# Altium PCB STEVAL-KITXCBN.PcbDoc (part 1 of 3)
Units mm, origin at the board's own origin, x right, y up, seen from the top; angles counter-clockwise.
Board outline 110 x 100 mm, 4 copper layers (Top Layer, GND, PWR, Bottom Layer), stack 1.53 mm thick; 227 components, 137 nets, 699 pads, 698 vias.
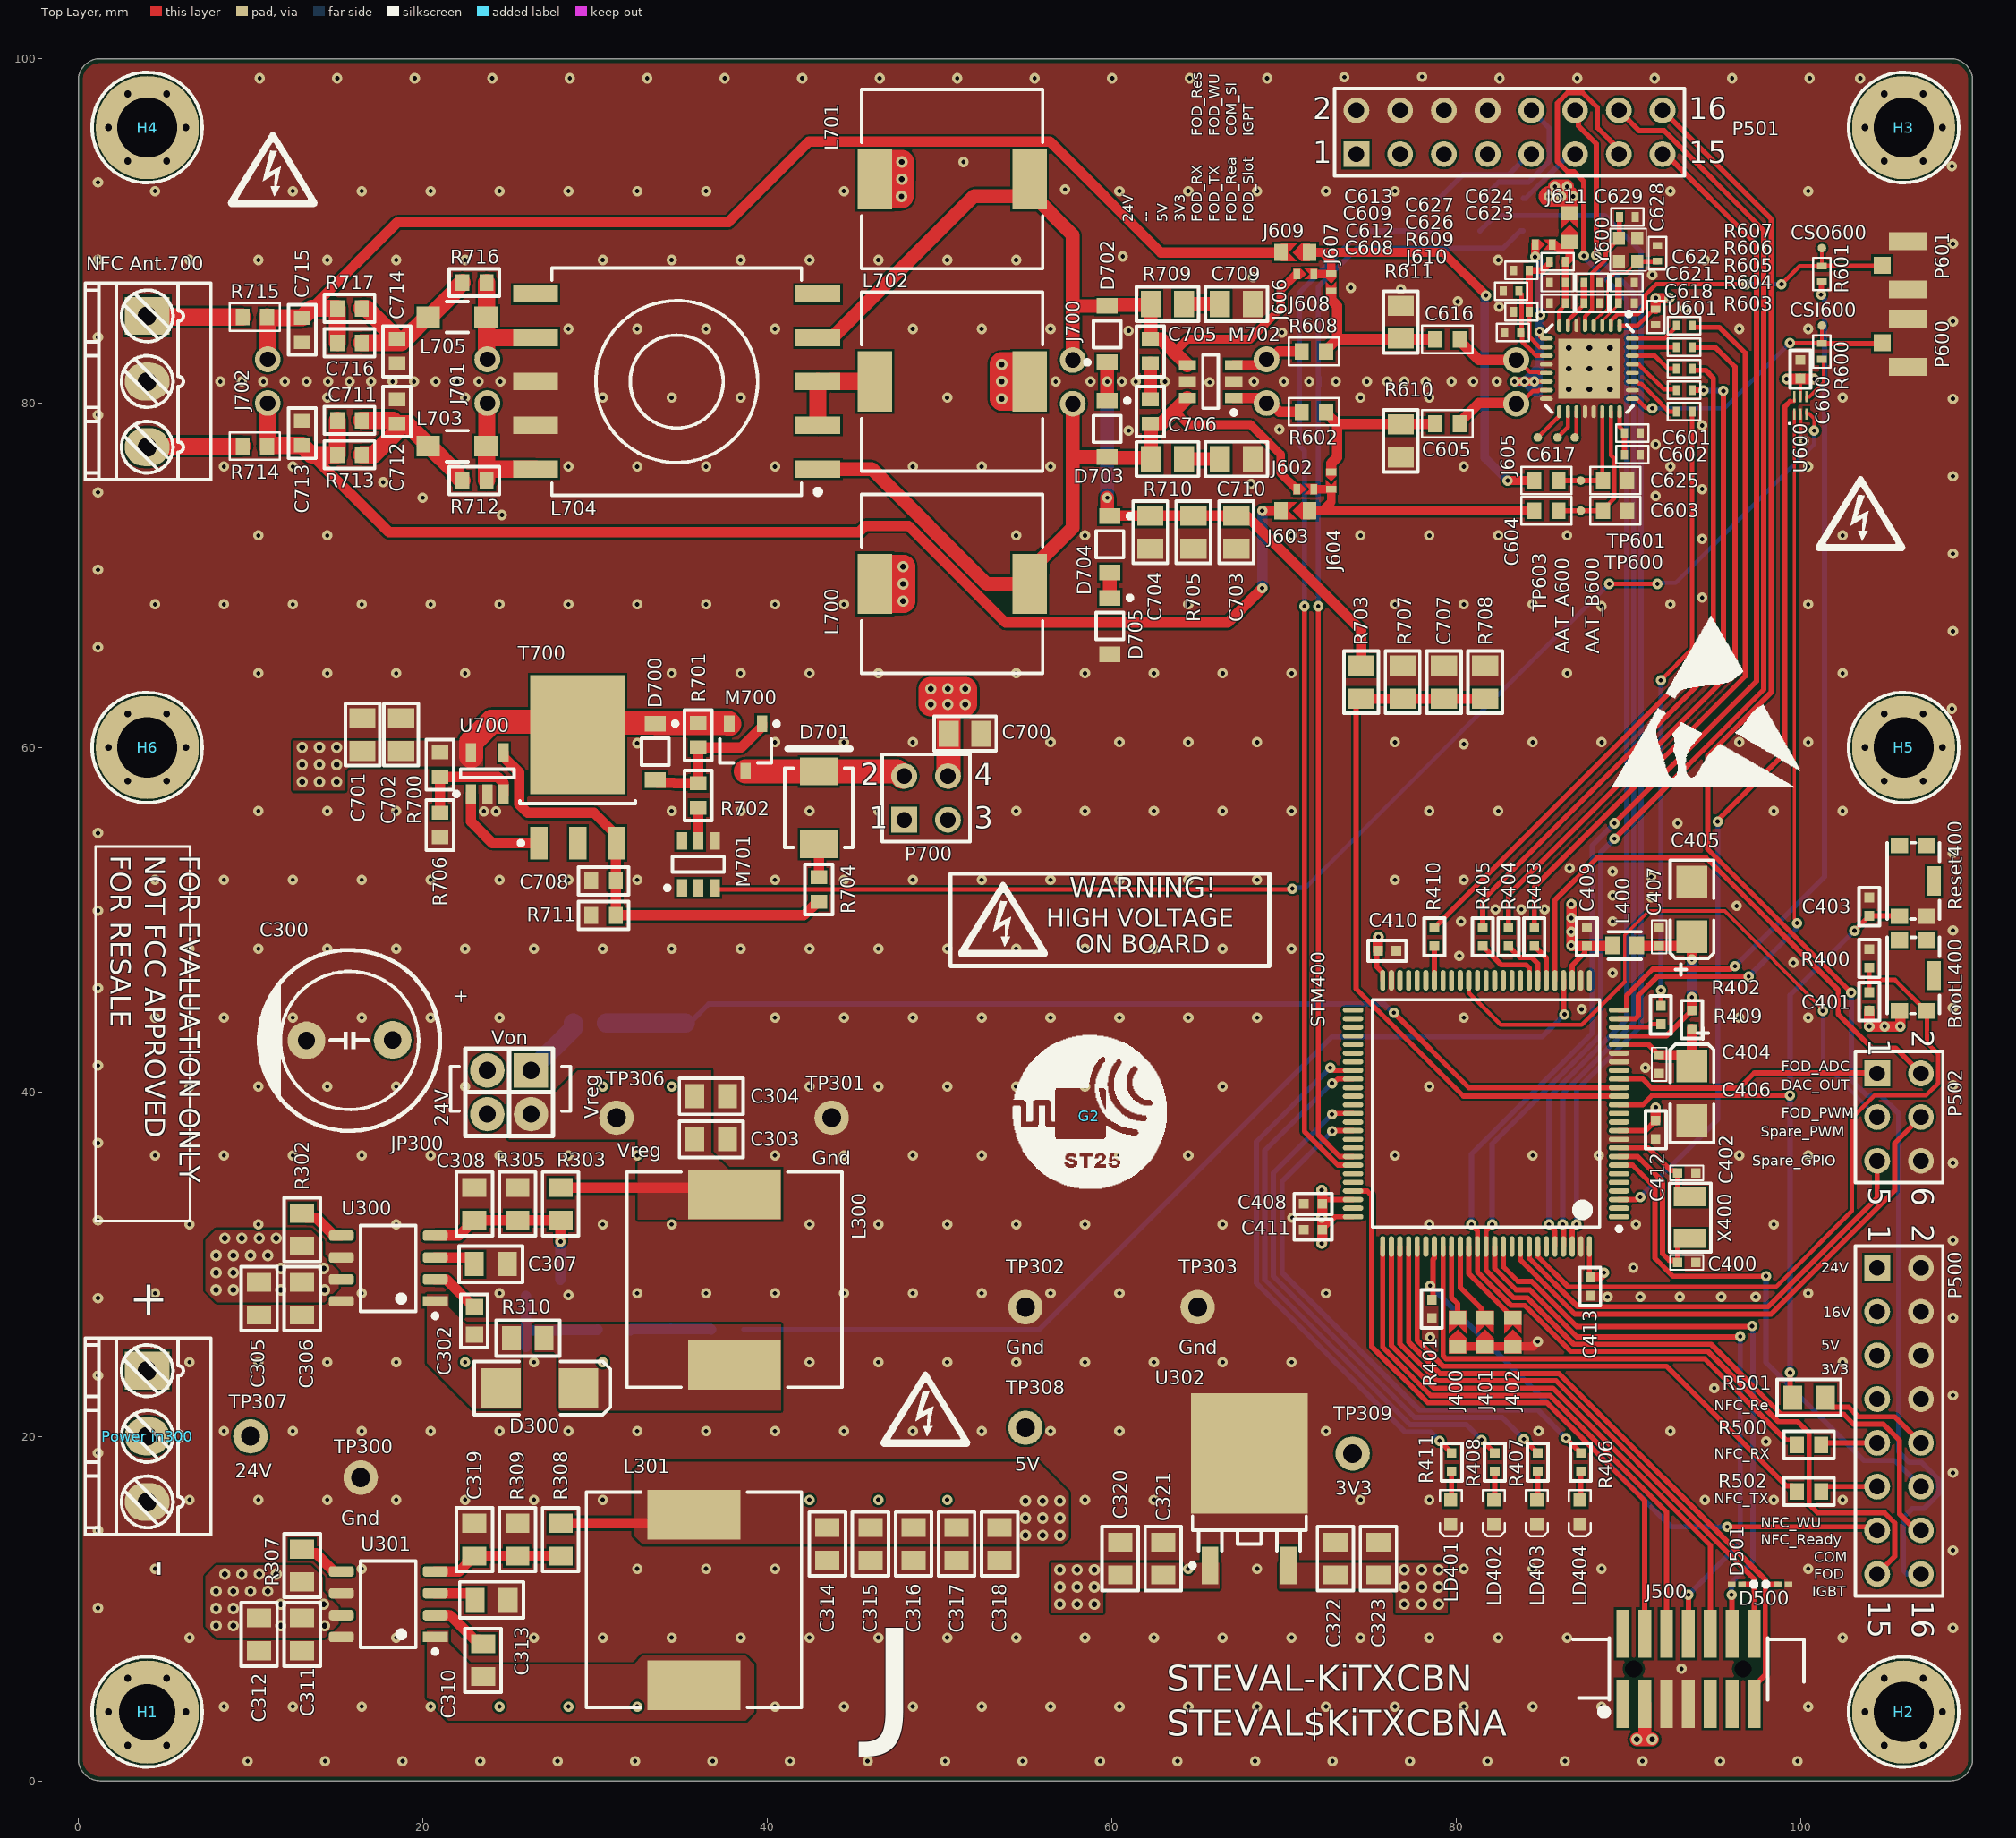
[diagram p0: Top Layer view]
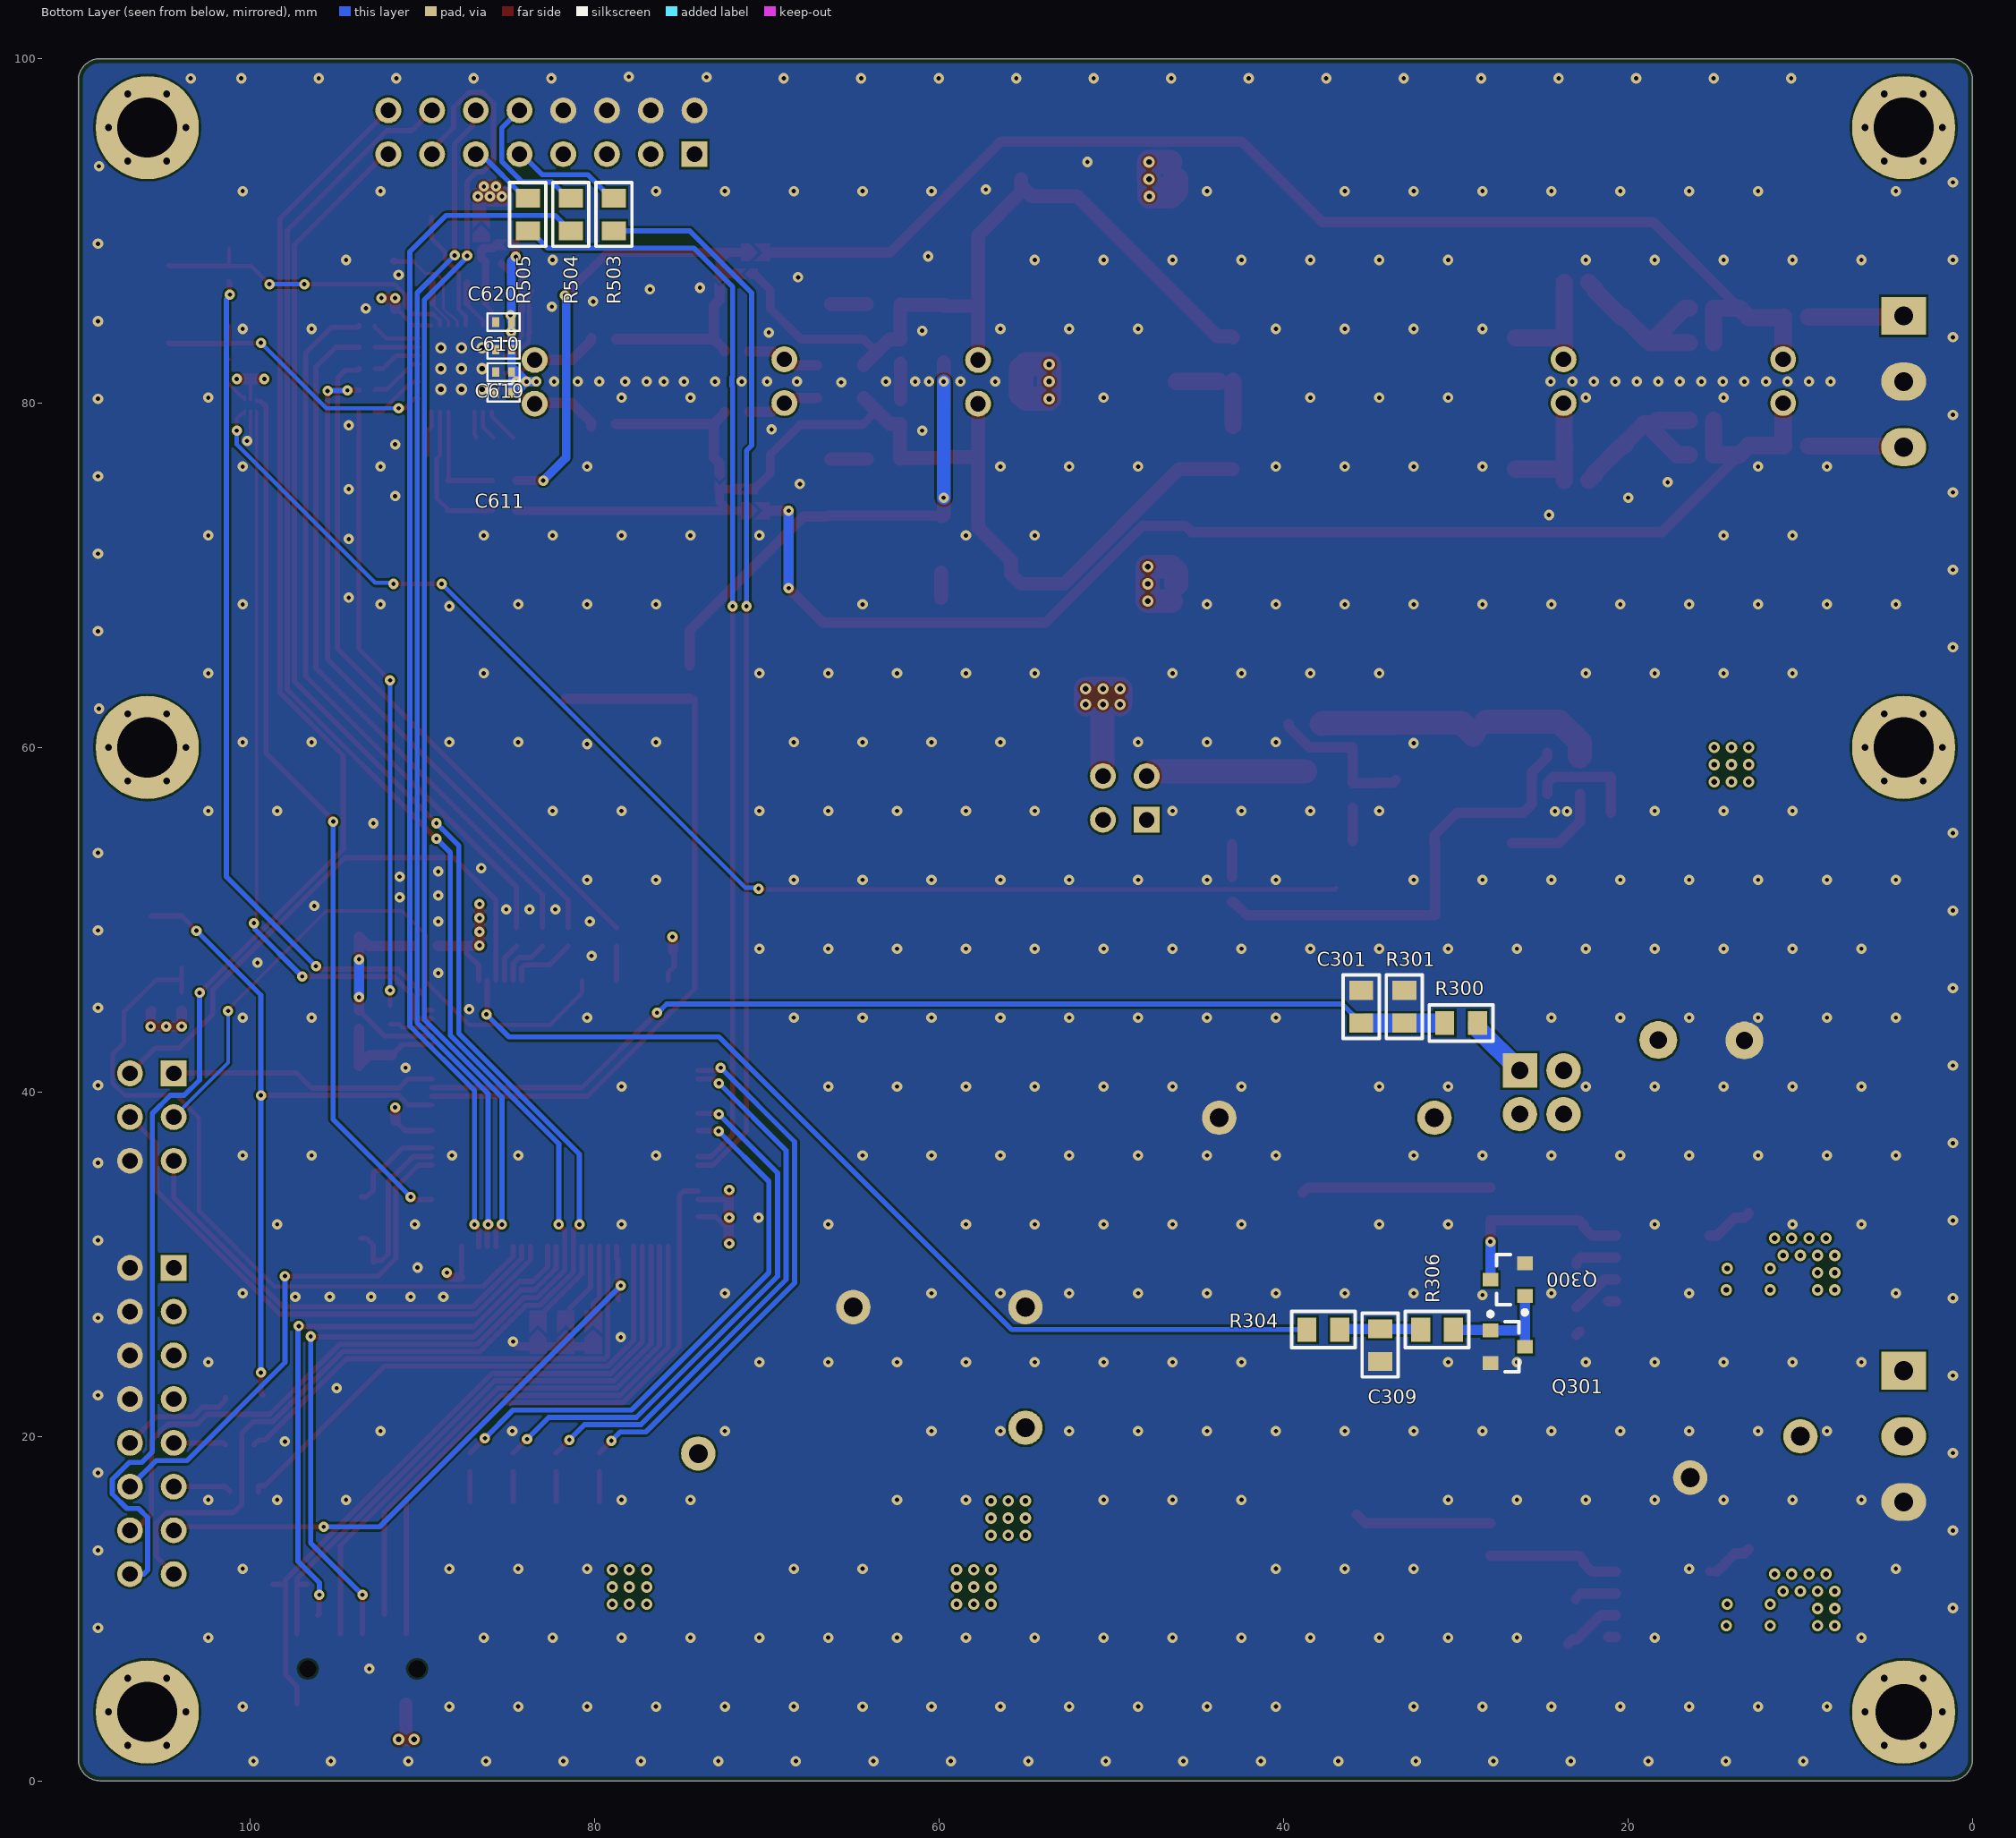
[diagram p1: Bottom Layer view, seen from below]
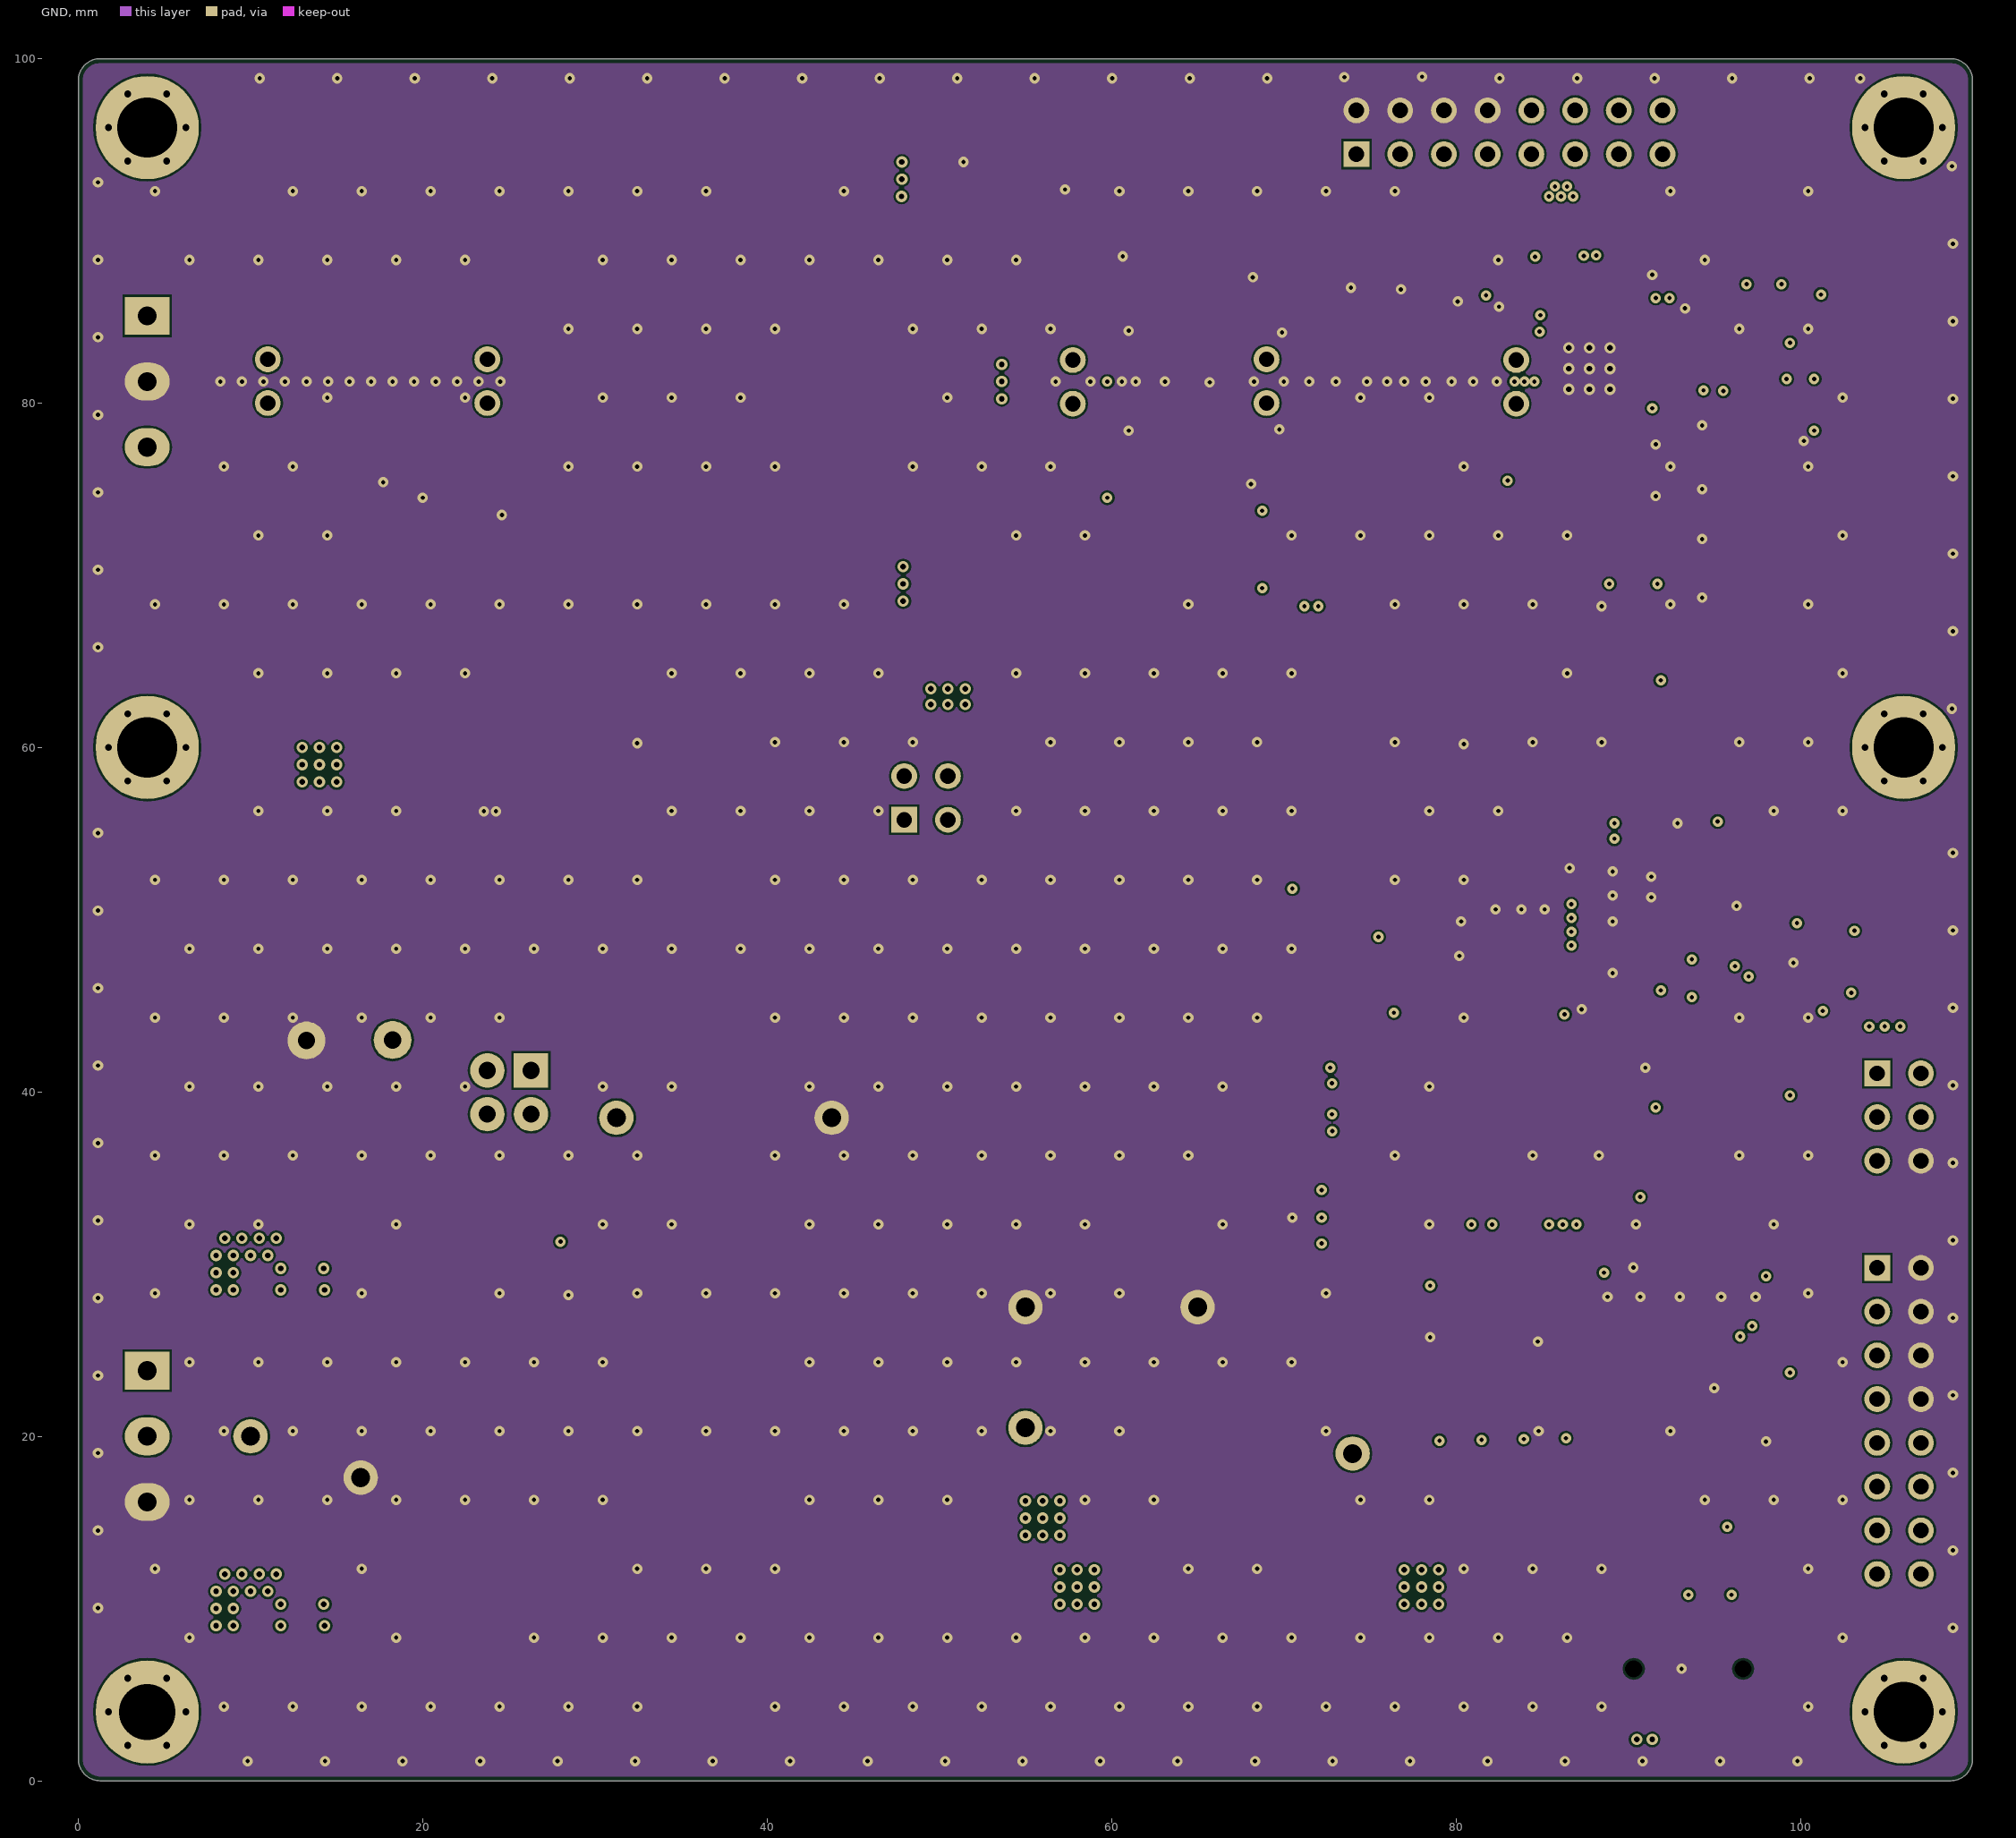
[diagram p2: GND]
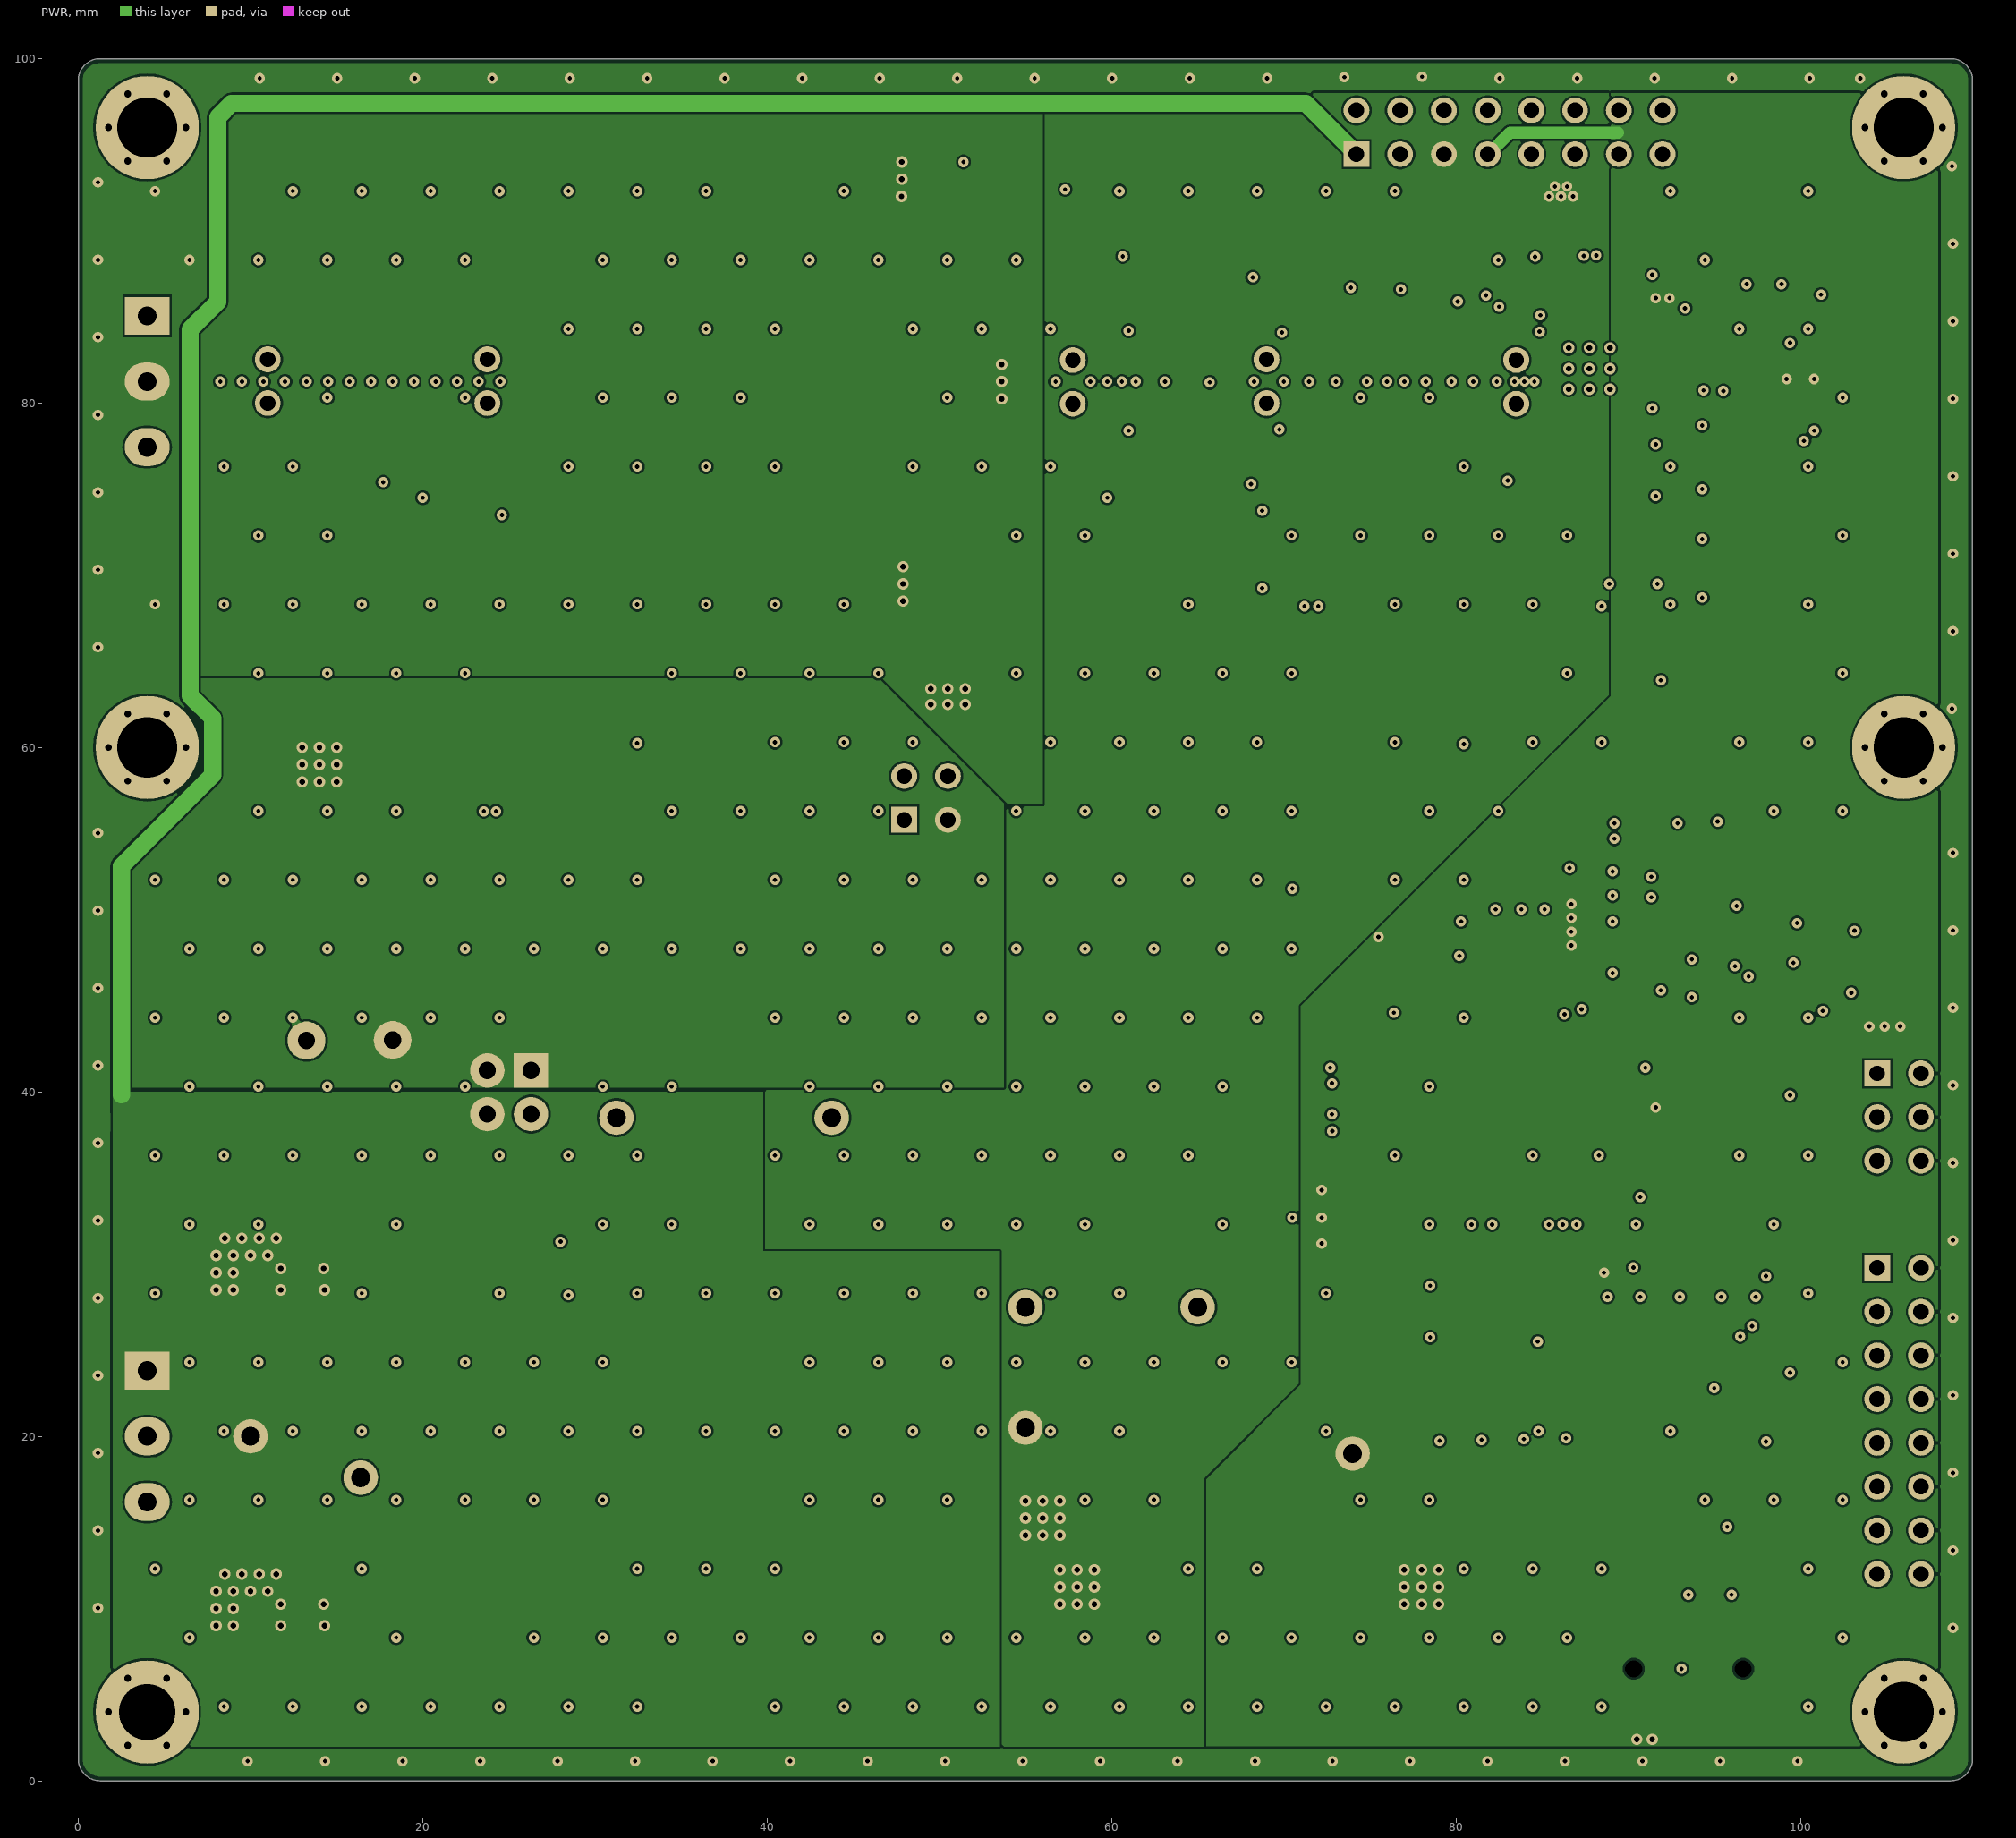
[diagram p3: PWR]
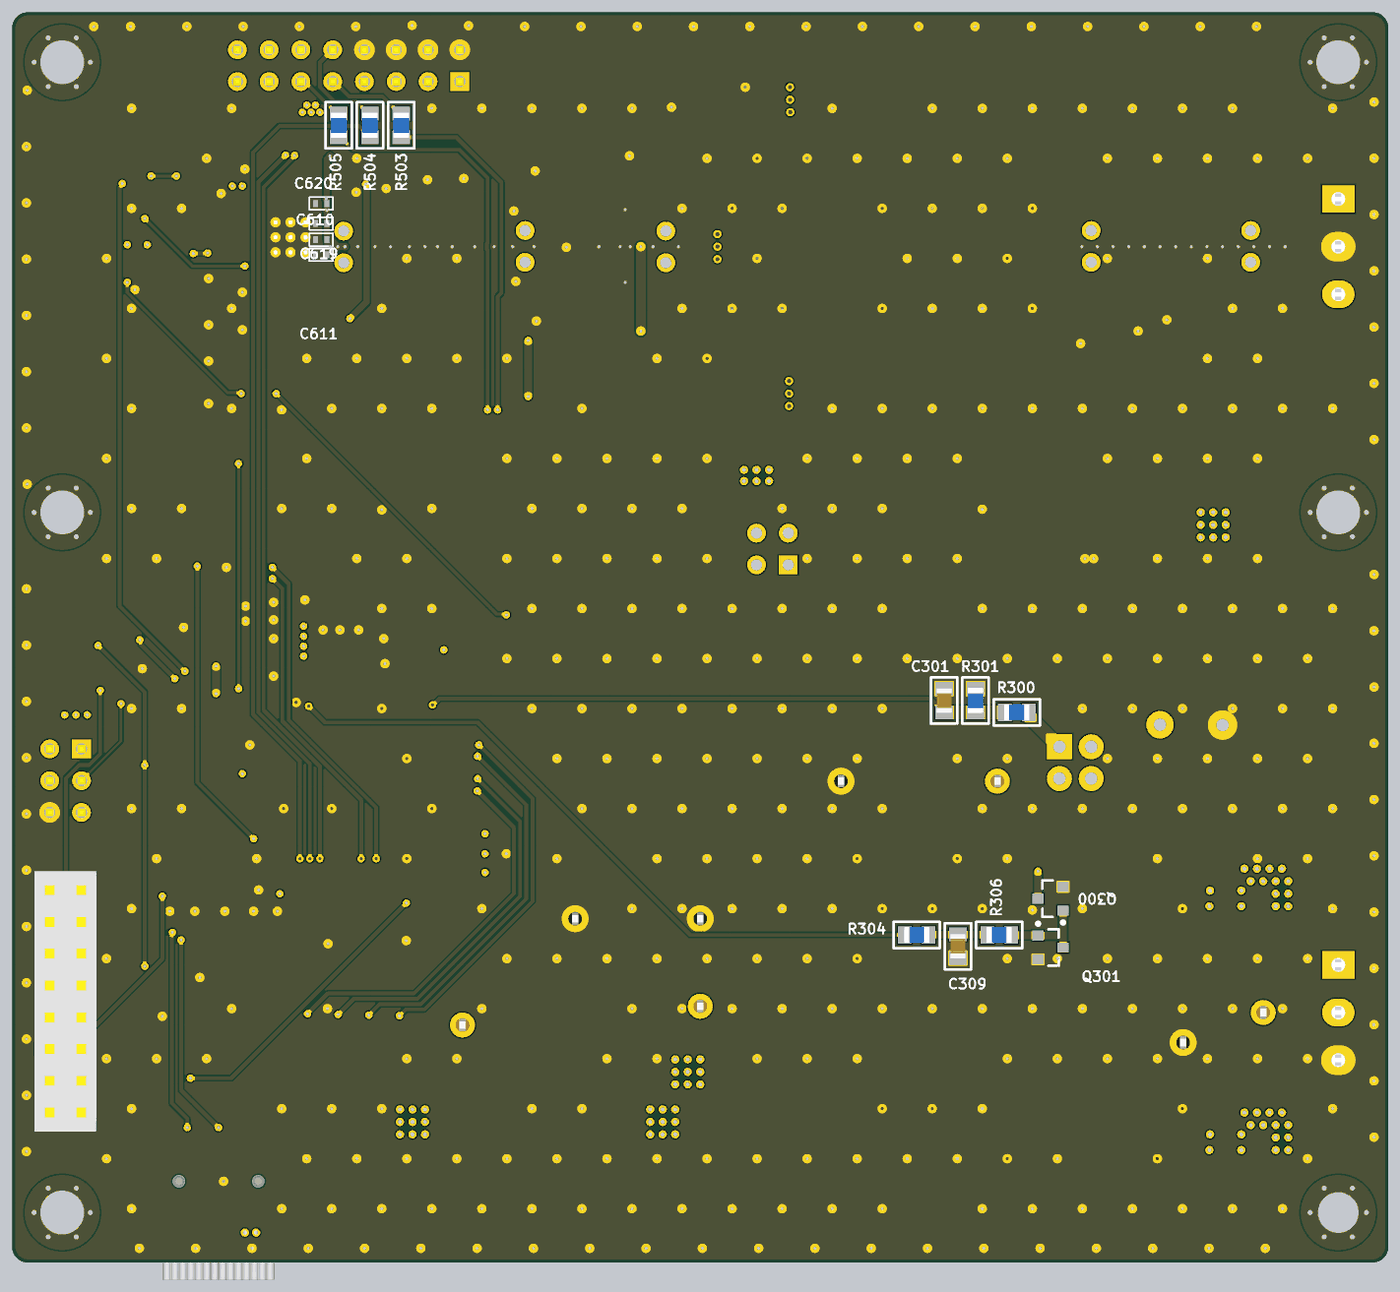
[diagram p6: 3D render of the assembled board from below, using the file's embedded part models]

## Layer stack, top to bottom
Top Solder: solder mask 0.01, Solder Resist, Dk 3.5
Top Layer: signal copper 0.035
Dielectric 1: core 0.62, FR-4, Dk 4.4
GND: signal copper 0.035
Dielectric 3: prepreg 0.15, RF-4, Dk 4.4
PWR: signal copper 0.035
Dielectric 2: core 0.62, RF-4, Dk 4.4
Bottom Layer: signal copper 0.035
Bottom Solder: solder mask 0.01, Solder Resist, Dk 3.5

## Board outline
0,1.27 0,98.73 cw(c1.27,98.73) 1.27,100 108.73,100 cw(c108.73,98.73) 110,98.73 110,1.27 cw(c108.73,1.27) 108.73,0 1.27,0 cw(c1.27,1.27)

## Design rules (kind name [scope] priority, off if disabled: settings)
BoardOutlineClearance [All] p1: gap=0.254 ignorepadtopadclearanceinfootprint=FALSE except(0: Arc-SplitContinuation Track-SplitContinuation SMDPad-SplitContinuation THPad-SplitContinuation Via-SplitContinuation Fill-SplitContinuation Poly-SplitContinuation Region-SplitContinuation Text-SplitContinuation)
Clearance "Stitching GND" [IsStitchingVia and InNet('GND') vs (IsVia and (Not IsStitchingVia)) Or IsPad] p1: gap=0.127 ignorepadtopadclearanceinfootprint=FALSE
Clearance [All] p2: gap=0.125 ignorepadtopadclearanceinfootprint=FALSE except(0: Arc-Hole Track-Hole SMDPad-Hole THPad-Hole Via-Hole Fill-Hole Poly-Hole Region-Hole Text-Hole)
DiffPairsRouting [All] p1: maxlimit=10 minlimit=0.125 mostfreqgap=0.15 toplayer_minwidth=0.381 toplayer_maxwidth=0.381 toplayer_prefwidth=0.381 midlayer1_minwidth=0.381 midlayer1_maxwidth=0.381 midlayer1_prefwidth=0.381 midlayer2_minwidth=0.381 midlayer2_maxwidth=0.381 midlayer2_prefwidth=0.381 bottomlayer_minwidth=0.381 bottomlayer_maxwidth=0.381 bottomlayer_prefwidth=0.381 maxuncoupledlength=12.7
FabricationTestPointUsage FabricationTestPointUsage_1 [All] p1: valid=0 allowmultiple=FALSE
FabricationTestpoint FabricationTestpoint_1 [All] p1: side=3 testpointundercomponent=TRUE minsize=1.016 maxsize=2.54 preferedsize=1.524 minholesize=0 maxholesize=1.016 preferedholesize=0.813 testpointgrid=0.025 allowsidetop=TRUE allowsidebottom=TRUE usegrid=TRUE gridtolerance=0
HoleSize [All] p1: absolutevalues=TRUE maxlimit=6 minlimit=0.2 maxpercent=80.000 minpercent=20.000
HoleSize FabricationTestpoint [All] p2 off: absolutevalues=TRUE maxlimit=2.54 minlimit=0.025 maxpercent=80.000 minpercent=20.000
HoleSize FabricationTestPointUsage [All] p3 off: absolutevalues=TRUE maxlimit=2.54 minlimit=0.025 maxpercent=80.000 minpercent=20.000
PlaneClearance [All] p1: clearance=0.5
PlaneConnect [All] p1: planeconnectstyle=Relief reliefexpansion=0.4 reliefentries=4 reliefconductorwidth=0.15 reliefairgap=0.15
PolygonConnect [All] p1: connectstyle=Direct reliefconductorwidth=0.15 reliefentries=4 polygonreliefangle="90 Angle" airgapwidth=0.254
RoutingCorners [All] p1: cornerstyle=45-Degree minsetback=1.25 maxsetback=1.25
RoutingVias [All] p1: holewidth=0.3 width=0.6 viastyle="Through Hole" minholewidth=0.2 minwidth=0.45 maxholewidth=0.45 maxwidth=0.75
SolderMaskExpansion SolderMaskExpansion_isvia [IsVia] p1: expansion=0.1 istentingtop=FALSE soldermaskfromhole=TRUE
SolderMaskExpansion [All] p2: expansion=0.075 istentingtop=FALSE
Width [All] p1: maxlimit=10 minlimit=0.125 preferedwidth=0.15
23 further rules are at their usual default settings.

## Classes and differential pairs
component class Designator: AAT_A600 AAT_B600 C600 C601 C602 C603 C604 C605 C608 C609 C610 C611 C612 C613 C616 C617 C618 C619 C620 C621 C622 C623 C624 C625 C626 C627 C628 C629 CSI600 CSO600 J602 J603 J604 J605 J606 J607 J608 J609 J610 J611 P600 P601 R600 R601 R602 R603 R604 R605 R606 R607 R608 R609 R610 R611 TP600 TP601 TP603 U600 U601 Y600
component class "Project Page_Ki_Main_V1_3": Coil1 D6 D8 D9 D10 D11 G2 H1 H2 H3 H4 H5 H6 J?1 R10 U?1

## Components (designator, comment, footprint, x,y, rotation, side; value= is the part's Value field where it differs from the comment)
AAT_A600 "*" TP_0.5 85.9,78 r90 top
AAT_B600 "*" TP_0.5 86.9,78 r90 top
BootL400 "PushButton" SW_SPST_KMR211G 107.35,44.7 r270 top
C300 "100uF" "ECAP 10XP5  H14" 15.75,43 r90 top
C301 "100nF" CAP_SMD_0805 35.5,44.95 r270 bottom
C302 "100nF" CAP_SMD_0603 23,26.7 r270 top
C303 "10uF" CAP_SMD_0805 36.75,37.25 r180 top
C304 "10uF" CAP_SMD_0805 36.75,39.75 r180 top
C305 "100nF" CAP_SMD_0805 10.5,28 r90 top
C306 "10uF" CAP_SMD_0805 13,28 r90 top
C307 "1uF" CAP_SMD_0805 23.95,30 r0 top
C308 "10pF" CAP_SMD_0805 23,33.5 r90 top
C309 "1uF" CAP_SMD_0805 34.4,25.3 r270 bottom
C310 "100nF" CAP_SMD_0805 23.5,7 r90 top
C311 "1uF" CAP_SMD_0805 13,8.5 r270 top
C312 "10uF" CAP_SMD_0805 10.5,8.5 r90 top
C313 "1uF" CAP_SMD_0805 24,10.5 r0 top
C314 "10uF" CAP_SMD_0805 43.5,13.75 r90 top
C315 "10uF" CAP_SMD_0805 46,13.75 r90 top
C316 "10uF" CAP_SMD_0805 48.5,13.75 r90 top
C317 "10uF" CAP_SMD_0805 51,13.75 r90 top
C318 "100nF" CAP_SMD_0805 53.5,13.75 r90 top
C319 "10pF" CAP_SMD_0805 23,14 r90 top
C320 "100nF" CAP_SMD_0805 60.5,12.9 r270 top
C321 "1uF" CAP_SMD_0805 63,12.9 r90 top
C322 "1uF" CAP_SMD_0805 73,12.9 r90 top
C323 "100nF" CAP_SMD_0805 75.5,12.9 r270 top
C400 "18pF" C0402#1 93.4,30.1 r0 top
C401 "100nF" C0402-ss 104,45.25 r90 top
C402 "18pF" C0402#1 93.4,35.3 r0 top
C403 "100nF" C0402-ss 104,50.75 r270 top
C404 "100nF" C0402#1 91.8,41.6 r270 top
C405 "1uF" CP_SMD_A 93.7,50.6 r90 top
C406 "1uF" CP_SMD_A 93.7,39.913 r270 top
C407 "100nF" C0402#1 91.8,49 r90 top
C408 "100nF" C0402-ss 71.7,33.5 r0 top
C409 "100nF" C0402-ss 87.6,49 r270 top
C410 "100nF" C0402-ss 76,48.2 r180 top
C411 "100nF" C0402-ss 71.7,32 r0 top
C412 "100nF" C0402-ss 91.6,37.8 r90 top
C413 "100nF" C0402-ss 87.8,28.7 r90 top
C600 "100nF" C0402-ss 100,81.965 r270 top
C601 "1uF" C0402#2 90.25,78.25 r0 top
C602 "10nF" C0402#2 90.25,77 r0 top
C603 "120pF" C0603 89.25,73.75 r180 top
C604 "10pF" C0603 85.25,73.75 r180 top
C605 "100nF" C0603 79.5,78.8 r180 top
C608 "10nF" C0402#2 83.3,84.1 r180 top
C609 "2u2F" C0402#2 83.2,86.5 r180 top
C610 "10nF" C0402#2 85.3,81.8 r0 bottom
C611 "4u7F" C0402#2 85.3,80.6 r0 bottom
C612 "10nF" C0402#2 83.8,85.3 r180 top
C613 "2u2F" C0402#2 83.8,87.7 r180 top
C616 "100nF" C0603 79.5,83.7 r180 top
C617 "10pF" C0603 85.25,75.5 r0 top
C618 "10nF" C0402#2 91.6,85 r270 top
C619 "d.n.p." C0402#2 85.3,83.1 r0 bottom
C620 "d.n.p." C0402#2 85.3,84.7 r0 bottom
C621 "10nF" C0402#2 89.9,85.8 r0 top
C622 "2u2F" C0402#2 89.9,87 r0 top
C623 "10nF" C0402#2 87.9,85.8 r0 top
C624 "2u2F" C0402#2 87.9,87 r0 top
C625 "120pF" C0603 89.25,75.5 r0 top
C626 "10nF" C0402#2 85.9,85.8 r180 top
C627 "2u2F" C0402#2 85.9,87 r180 top
C628 "10pF" C0402#2 91.7,88.7 r90 top
C629 "10pF" C0402#2 89.957,90.8 r0 top
C700 "1nF" C0805 51.5,60.8 r0 top
C701 "10µF" C0805 16.5,60.75 r90 top
C702 "10nF" C0805 18.75,60.75 r90 top
C703 "100nF" C0805 67.25,72.5 r270 top
C704 "68pF" C0805 62.25,72.5 r270 top
C705 "15pF" C0603 62.25,83 r270 top
C706 "22pF" C0603 62.25,79.5 r270 top
C707 "100nF" C0805 79.3,63.8 r90 top
C708 "47nF" C0603 30.5,52.25 r0 top
C709 "33pF" C0805 67.25,85.75 r0 top
C710 "33pF" C0805 67.25,76.75 r0 top
C711 "2n2F" C0603 15.75,79 r180 top
C712 "22pF" C0603 18.5,79.5 r90 top
C713 "130pF" C0603 13,78.25 r90 top
C714 "22pF" C0603 18.5,83 r90 top
C715 "130pF" C0603 13,84.25 r90 top
C716 "2n2F" C0603 15.75,83.5 r180 top
CSI600 "*" TP_0.5 101.25,84.5 r90 top
CSO600 "*" TP_0.5 101.25,89 r90 top
D300 "Schottky" SMB 26.8,22.8 r0 top
D500 "ESDALC6V1-1U2" ST-ST0201 99,11.4 r90 top
D501 "ESDALC6V1-1U2" ST-ST0201 96.3,11.4 r270 top
D700 "" ONSC-SOD-123-2-425-04_V 33.5,59.75 r270 top
D701 "STPS2L25U" STM-SMB_P_V 43,56.5 r90 top
D702 "MMSD4148T1G" ONSC-SOD-123-2-425-04_V 59.75,84 r90 top
D703 "MMSD4148T1G" ONSC-SOD-123-2-425-04_V 59.75,78.5 r270 top
D704 "" ONSC-SOD-123-2-425-04_V 59.9,71.8 r270 top
D705 "" ONSC-SOD-123-2-425-04_V 59.9,67.05 r270 top
G2 "Logo_ST25" Logo_ST25 58.7,38.6 r0 top
H1 "Mounting Hole" HOLE_M3#1 4,4 r0 top
H2 "Mounting Hole" HOLE_M3#2 106,4 r0 top
H3 "Mounting Hole" HOLE_M3#2 106,96 r0 top
H4 "Mounting Hole" HOLE_M3#2 4,96 r0 top
H5 "Mounting Hole" HOLE_M3#2 106,60 r0 top
H6 "Mounting Hole" HOLE_M3#2 4,60 r0 top
J400 "open" JP2_SMD_open 80.1,26.05 r90 top
J401 "open" JP2_SMD_open 81.7,26.05 r90 top
J402 "open" JP2_SMD_open 83.3,26.05 r90 top
J500 "FTSH-107-01-L-DV-K-A" SAMTEC-FTSH-107-01-X-DV-K-A-WITH-FFSD 93.5,6.5 r0 top
J602 "open" JP2_SMD_open_0402 71.25,75 r0 top net-tie
J603 "closed 0R" JP2_SMD_closed 70.668,73.75 r180 top net-tie
J604 "open" JP2_SMD_open_0402 72.75,75.5 r270 top net-tie
J605 "d.n.p." HDR1X2_slim 83.5,79.96 r270 top
J606 "d.n.p." HDR1X2_slim 69,80 r270 top
J607 "open" JP2_SMD_open_0402 72.75,87 r270 top net-tie
J608 "open" JP2_SMD_open_0402 71.25,87.5 r0 top net-tie
J609 "closed 0R" JP2_SMD_closed 70.668,88.75 r180 top net-tie
J610 "open" JP2_SMD_open_0402 85.1,89.2 r0 top net-tie
J611 "closed 0R" JP2_SMD_closed 86.6,90.2 r90 top net-tie
J700 "d.n.p." HDR1X2_slim 57.75,79.96 r270 top
J701 "d.n.p." HDR1X2_slim 23.75,80 r270 top
J702 "d.n.p." HDR1X2_slim 11,80 r270 top
JP300 "TSW-102-07-G-D" Jump2V 26.29,41.25 r180 top
L300 "56uH" WE-PD-L 38.1,29.1 r90 top
L301 "33uH" WE-PD-L 35.75,10.5 r90 top
L400 "Ferrite Bead" 0603-CAP 89.8,48.5 r90 top value=BLM18AG601SN1D
L700 "7447714100" "WE-PD 1050" 50.75,69.5 r180 top value=10u
L701 "7447714100" "WE-PD 1050" 50.75,93 r180 top value=10u
L702 "7447714100" "WE-PD 1050" 50.75,81.25 r0 top value=10u
L703 "470n" FP-LQM31PN_00-MFG 22,77.5 r180 top
L704 "Cooktop Balun" "Wurth Cooktop Balun" 34.75,81.25 r180 top value=Balun
L705 "470n" FP-LQM31PN_00-MFG 22,85 r180 top
LD401 "White LED" 0603D 79.7,15.6 r270 top
LD402 "White LED" 0603D 82.2,15.6 r270 top
LD403 "White LED" 0603D 84.7,15.6 r270 top
LD404 "White LED" 0603D 87.2,15.6 r270 top
M700 "SSM3J353F,LF" "RSR020P05 SOT23-3L" 38.75,60 r270 top
M701 "NMOS STT6N3LLH6" "STT6N3LLH6 SOT23-6L" 36,53.211 r90 top
M702 "QS6K21FRATR" "NDC7002N TSOT23 6-Lead" 65.75,81.25 r180 top
"NFC Ant.700" "Screw Terminal" "TERMINAL MKDS 1/ 3-3.81" 4,81.25 r90 top locked value="MKDS 1/3-3.81"
P500 "Header 8X2_3D_female" HDR2X8_3D_female 104.46,29.78 r270 top
P501 "Header 8X2_3D_male" HDR2X8_3D_male 74.22,94.455 r0 top
P502 "Header 3X2_3D_male" HDR2X3_3D_male 104.46,41.08 r270 top
P600 "U.FL-R-SMT-1" "U FL Socket - HRS - Surface Mount" 105.75,83.5 r180 top
P601 "U.FL-R-SMT-1" "U FL Socket - HRS - Surface Mount" 105.75,88 r180 top
P700 "Header 2X2" HDR2X2 47.96,55.8 r0 top value=0
"Power in300" "Screw Terminal" "TERMINAL MKDS 1/ 3-3.81" 4,20 r90 top locked value="MKDS 1/3-3.81"
Q300 "BC846BLT1G" ONSC-SOT-23-3-318-08_V 27,29.1 r0 bottom
Q301 "BC846BLT1G" ONSC-SOT-23-3-318-08_V 27,25.2 r180 bottom
R300 "100k" RES_SMD_0805 29.7,44 r180 bottom
R301 "10k" RES_SMD_0805 33,44.95 r270 bottom
R302 "10k" RES_SMD_0805 13,32 r270 top
R303 "150k" RES_SMD_0805 28,33.5 r90 top
R304 "1k" RES_SMD_0805 37.7,26.2 r180 bottom
R305 "33k" RES_SMD_0805 25.5,33.5 r270 top
R306 "20k" RES_SMD_0805 31.1,26.2 r0 bottom
R307 "10k" RES_SMD_0805 13,12.5 r270 top
R308 "402kR" RES_SMD_0805 28,14 r90 top
R309 "82kR" RES_SMD_0805 25.5,14 r270 top
R310 "820" RES_SMD_0805 26.1,25.7 r180 top
R400 "10kR" R0402#1 104,47.75 r270 top
R401 "10kR" R0402#1 78.6,27.4 r90 top
R402 "0R" R0402#1 91.9,44.467 r270 top
R403 "0R" R0402#1 84.55,49 r270 top
R404 "0R" R0402#1 83.05,49 r270 top
R405 "0R" R0402#1 81.55,49 r270 top
R406 "120R" R0402#1 87.25,18.5 r270 top
R407 "120R" R0402#1 84.75,18.5 r270 top
R408 "120R" R0402#1 82.25,18.5 r270 top
R409 "47R" R0402#1 93.7,44.2 r270 top
R410 "0R" R0402#1 78.75,49 r270 top
R411 "120R" R0402#1 79.75,18.5 r270 top
R500 "100R" R0603 100.5,19.5 r0 top
R501 "220R" RES_SMD_0805 100.5,22.25 r180 top
R502 "100R" R0603 100.5,16.8 r0 top
R503 "0R" RES_SMD_0805 78.9,90.95 r90 bottom
R504 "220R" RES_SMD_0805 81.4,90.95 r270 bottom
R505 "0R" RES_SMD_0805 83.9,90.95 r90 bottom
R600 "50R" R0402#2 101.25,83 r90 top
R601 "50R" R0402#2 101.25,87.5 r90 top
R602 "0R" R0603 71.75,79.5 r180 top
R603 "0R" R0402#2 93.25,79.5 r0 top
R604 "0R" R0402#2 93.25,80.75 r0 top
R605 "0R" R0402#2 93.25,82 r0 top
R606 "0R" R0402#2 93.25,83.25 r0 top
R607 "0R" R0402#2 93.25,84.5 r0 top
R608 "0R" R0603 71.75,83 r180 top
R609 "0R" R0402#2 85.9,88.2 r180 top
R610 "10kR" R0805 76.8,77.8 r270 top
R611 "10kR" R0805 76.8,84.7 r270 top
R700 "10k" R0603 21,59 r270 top
R701 "2k" R0603 36,60.711 r270 top
R702 "4k2" R0603 36,57.211 r270 top
R703 "330kR" R0805 74.5,63.8 r270 top
R704 "2R" R0603 43,51.75 r270 top value=2
R705 "10kR" R0805 64.75,72.5 r270 top
R706 "40k2" R0603 21,55.5 r270 top
R707 "10kR" R0805 76.9,63.8 r90 top
R708 "d.n.p." R0805 81.7,63.8 r90 top
R709 "10R" R0805 63.25,85.75 r0 top
R710 "10R" R0805 63.25,76.75 r0 top
R711 "47kR" R0603 30.5,50.25 r180 top
R712 "100R" R0603 23,75.5 r180 top
R713 "1M" R0603 15.75,77 r180 top
R714 "0R" R0603 10.25,77.5 r180 top
R715 "0R" R0603 10.25,85 r180 top
R716 "100R" R0603 23,87 r180 top
R717 "1M" R0603 15.75,85.5 r180 top
Reset400 "PushButton" SW_SPST_KMR211G 107.35,50.2 r270 top
STM400 "STM32L476VGT6" "STM32L476VGT6 LQFP100" 81.75,38.75 r180 top
T700 "NPN STD1802T4" "STD1802 DPAK" 29,58.85 r90 top
TP300 "Gnd" TESTPOINT_BLACK 16.4,17.6 r90 top value=Testpoint
TP301 "Gnd" TESTPOINT_BLACK 43.75,38.5 r90 top value=Testpoint
TP302 "Gnd" TESTPOINT_BLACK 55,27.5 r90 top value=Testpoint
TP303 "Gnd" TESTPOINT_BLACK 65,27.5 r90 top value=Testpoint
TP306 "Vreg" TESTPOINT_RED 31.25,38.5 r90 top value=Testpoint
TP307 "24V" TESTPOINT_RED 10,20 r90 top value=Testpoint
TP308 "5V" TESTPOINT_RED 55,20.5 r90 top value=Testpoint
TP309 "3V3" TESTPOINT_RED 74,19 r90 top value=Testpoint
TP600 "*" TP_0.5 87.25,73.75 r90 top
TP601 "*" TP_0.5 87.25,75.5 r90 top
TP603 "*" TP_0.5 84.75,78 r90 top
U300 "L6981NDR" SOIC-8 18,29.75 r180 top
U301 "L6981NDR" SOIC-8 18,10.25 r180 top
U302 "LF33CDT" "TO-252 DPAK" 68,16.9 r0 top
U600 "74LVC1G3157" XSON6_SOT1202 100,79.865 r90 top
U601 "ST25R3916" ST25R3916-QFN32_5X5_0.5 87.75,82 r270 top
U700 "THS4304DBVTG4" TI-DBV5_N 23.75,58.5 r90 top
X400 "32_768kHz" 32_768kHz_Crystal 93.6,32.7 r270 top
Y600 "NDK 27,12MHz Crystal" XRCGB_F_MN 90,88.9 r90 top

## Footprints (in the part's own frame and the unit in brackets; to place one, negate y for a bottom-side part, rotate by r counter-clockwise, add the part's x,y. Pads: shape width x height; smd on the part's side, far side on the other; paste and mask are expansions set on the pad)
32_768kHz_Crystal [mm]
  rect 1.1x1.9 smd paste+0: 1(-1.2,0) 2(1.2,0)
  silkscreen extent -2,-1.2 2,1.2, body extent -1.6,-0.8 1.6,0.8, height 0.9
0603-CAP [mil]
  rect 41x35 smd: 1(0,-27) 2(0,27)
  silkscreen extent -31,-37 31,38, body extent -15,-39 16,39, height 31
0603D [mil]
  rect 30x30 smd: 1(27.5,0) 2(-27.5,0)
  silkscreen extent -50,-25 55,25
C0402#1 [mil]
  rect 22x22 smd paste+0 mask+0: 1(-21,0) 2(21,0)
  silkscreen extent -38,-17 38,17, body extent -27,-11 27,11, height 12
C0402#2 [mil]
  rect 15.75x22 smd paste+0 mask+0: 1(-18,0) 2(18,0)
  silkscreen extent -37,-20 37,20, body extent -26,-11 26,11, height 12
C0402-ss [mil]
  rect 22x22 smd paste+0 mask+0.39: 1(-21,0) 2(21,0)
  silkscreen extent -43,-24 43,24, body extent -27,-11 27,11, height 12
C0603 [mil]
  rect 32x38 smd paste+0 mask+0: 1(-28,0) 2(28,0)
  silkscreen extent -58,-31 58,31, body extent -38,-19 40,19, height 20
C0805 [mil]
  rect 46x60 smd paste+0 mask+0: 1(-37.5,0) 2(37.5,0)
  silkscreen extent -71,-39 71,39, body extent -53,-30 57,30, height 25
CAP_SMD_0603 [mm]
  rect 0.95x1 smd: 1(-0.8,0) 2(0.8,0)
  silkscreen extent -1.55,-0.78 1.55,0.78, body extent -0.8,-0.4 0.8,0.4, height 0.8
CAP_SMD_0805 [mm]
  rect 1.1x1.4 smd: 1(-0.95,0) 2(0.95,0)
  silkscreen extent -1.85,-1.05 1.85,1.05, body extent -1,-0.62 1,0.63, height 1
CP_SMD_A [mil]
  rect 75x70 smd paste+0 mask+0: 1(-62.5,0) 2(62.5,0)
  silkscreen extent -150,-50 112,50, body extent -62,-31 64,32, height 63
"ECAP 10XP5  H14" [mm]
  round 2.2 hole 1: 1(0.013,-2.5) 2(-0.013,2.5)
  silkscreen extent -5.26,-5.25 5.24,5.25, body extent -5.27,-5.26 5.25,5.26, height 14
FP-LQM31PN_00-MFG [mm]
  rect 1.35x1.2 smd paste+0 mask+0: 1(-1.675,0) 2(1.675,0)
  silkscreen extent -0.63,-0.9 0.63,0.9, body extent -1.6,-0.8 1.6,0.8, height 0.95
HDR1X2_slim [mm] "Connector; Header; 2 Position"
  round 1.5 hole 0.9: 1(0,0) 2(-2.54,0)
HDR2X2 [mm] "Connector; Header; 2x2 Position"
  rect 1.5x1.5 hole 0.9: 1(0,0)
  round 1.5 hole 0.9: 2(0,2.54) 3(2.54,0) 4(2.54,2.54)
  silkscreen extent -1.27,-1.27 3.81,3.81
HDR2X3_3D_male [mm] "Connector; Header; 3x2 Position"
  rect 1.5x1.5 hole 0.9: 1(0,0)
  round 1.5 hole 0.9: 2(0,2.54) 3(2.54,0) 4(2.54,2.54) 5(5.08,0) 6(5.08,2.54)
  silkscreen extent -1.27,-1.27 6.35,3.81, body extent -1.27,-1.27 6.35,3.81, height 8.42
HDR2X8_3D_female [mm] "Connector; Header; 8x2 Position"
  rect 1.5x1.5 hole 0.9: 1(0,0)
  round 1.5 hole 0.9: 2(0,2.54) 3(2.54,0) 4(2.54,2.54) 5(5.08,0) 6(5.08,2.54) 7(7.62,0) 8(7.62,2.54) 9(10.16,0) 10(10.16,2.54) 11(12.7,0) 12(12.7,2.54) 13(15.24,0) 14(15.24,2.54) 15(17.78,0) 16(17.78,2.54)
  silkscreen extent -1.27,-1.27 19.05,3.81, body extent -1.53,-1.2 19.3,3.75, height 8.46
HDR2X8_3D_male [mm] "Connector; Header; 8x2 Position"
  rect 1.5x1.5 hole 0.9: 1(0,0)
  round 1.5 hole 0.9: 2(0,2.54) 3(2.54,0) 4(2.54,2.54) 5(5.08,0) 6(5.08,2.54) 7(7.62,0) 8(7.62,2.54) 9(10.16,0) 10(10.16,2.54) 11(12.7,0) 12(12.7,2.54) 13(15.24,0) 14(15.24,2.54) 15(17.78,0) 16(17.78,2.54)
  silkscreen extent -1.27,-1.27 19.05,3.81, body extent -1.27,-1.24 19.05,3.78, height 8.43
HOLE_M3#1 [mm]
  round 0.4 hole 0.4 mask+0: 1(-2.25,0) 1(-1.125,-1.949) 1(-1.125,1.949) 1(1.125,-1.949) 1(1.125,1.949) 1(2.25,0)
  round 6 hole 3.25 mask+0.1: 1(0,0)
  silkscreen extent -3.2,-3.2 3.2,3.2
HOLE_M3#2 [mm]
  round 0.4 hole 0.4 mask+0: 1(-2.25,0) 1(-1.125,-1.949) 1(-1.125,1.949) 1(1.125,-1.949) 1(1.125,1.949) 1(2.25,0)
  round 6 hole 3.5 mask+0.1: 1(0,0)
  silkscreen extent -3.2,-3.2 3.2,3.2
JP2_SMD_closed [mm]
  rect 0.8x1 smd: 1(-0.832,0) 2(0.832,0)
  Top Layer region: -0.832,-0.5 -0.832,0.5 -0.348,0.5 0.152,0 -0.348,-0.5
  Top Layer region: -0.087,0.5 0.413,0 -0.087,-0.5 0.832,-0.5 0.832,0.5
  Top Layer pour cut-out: 1.375,0.625 1.375,-0.625 -1.375,-0.625 -1.375,0.625
  body extent -1.15,-0.38 1.1,0.37, height 0.3
JP2_SMD_open [mm]
  rect 0.8x1 smd paste-10: 1(-0.832,0) 2(0.832,0)
  Top Layer region: -1.25,-0.5 -1.25,0.5 -0.348,0.5 0.152,0 -0.348,-0.5
  Top Layer region: -0.087,0.5 0.413,0 -0.087,-0.5 1.25,-0.5 1.25,0.5
  Top Layer pour cut-out: 1.375,0.625 1.375,-0.625 -1.375,-0.625 -1.375,0.625
JP2_SMD_open_0402 [mm]
  rect 0.4x0.6 smd mask+0.05: 1(-0.5,0) 2(0.5,0)
  Top Layer region: -0.7,-0.3 -0.7,0.3 -0.25,0.3 0.05,0 -0.25,-0.3
  Top Layer region: -0.04,0.3 0.26,0 -0.04,-0.3 0.7,-0.3 0.7,0.3
Jump2V [mm]
  rect 2x2 hole 1: 1(0,0)
  round 2 hole 1: 2(0,2.54) 3(2.54,0) 4(2.54,2.54)
  silkscreen extent -1.27,-1.27 3.81,3.81
Logo_ST25 [mm] "Silk Only"
  silkscreen extent -4.44,-4.19 4.5,4.7
"NDC7002N TSOT23 6-Lead" [mm] "SOT23, 6-Leads, Body 2,95x2,75mm, Pitch 0,95mm, IPC Medium Density"
  rect 1x0.6 smd: 1(-1.35,0.95) 2(-1.35,0) 3(-1.35,-0.95) 4(1.35,-0.95) 5(1.35,0) 6(1.35,0.95)
  silkscreen extent -1.48,-1.55 0.45,1.92, body extent -0.85,-1.55 0.85,1.55, height 1.1
ONSC-SOD-123-2-425-04_V [mm] "SOD, 2-Leads, Body 2.69x1.6mm"
  rect 0.91x1.22 smd: 1(-1.635,0) 2(1.635,0)
  silkscreen extent -1.76,-0.8 0.78,1.29, body extent -1.35,-0.8 1.35,0.8, height 1.35
ONSC-SOT-23-3-318-08_V [mm] "SOT23, 3-Leads, Body 2.92x1.3mm, Pitch 0.95mm"
  rect 0.9x0.8 smd: 1(-1,0.95) 2(-1,-0.95) 3(1,0)
  silkscreen extent -1.12,-1.46 0.65,2.02, body extent -0.65,-1.46 0.65,1.46, height 1.11
R0402#1 [mil]
  rect 22x22 smd paste+0 mask+0: 1(-21,0) 2(21,0)
  silkscreen extent -43,-24 43,24, body extent -27,-11 27,11, height 12
R0402#2 [mil]
  rect 15.75x22 smd paste+0 mask+0: 1(-18,0) 2(18,0)
  silkscreen extent -37,-20 37,20, body extent -27,-11 27,11, height 12
R0603 [mil]
  rect 32x38 smd paste+0 mask+0: 1(-28,0) 2(28,0)
  silkscreen extent -58,-31 58,31, body extent -38,-19 40,19, height 20
R0805 [mil]
  rect 46x60 smd paste+0 mask+0: 1(-37.5,0) 2(37.5,0)
  silkscreen extent -71,-39 71,39, body extent -53,-30 57,30, height 25
RES_SMD_0805 [mm]
  rect 1.1x1.4 smd: 1(-0.95,0) 2(0.95,0)
  silkscreen extent -1.85,-1.05 1.85,1.05, body extent -1,-0.62 1,0.63, height 0.6
"RSR020P05 SOT23-3L" [mm]
  rect 0.95x0.6 smd: 1(-1.375,0.95) 2(-1.375,-0.95) 3(1.375,0)
  silkscreen extent -1.5,-1.5 0.9,1.93, body extent -0.9,-1.5 0.9,1.5, height 1
SAMTEC-FTSH-107-01-X-DV-K-A-WITH-FFSD [mm]
  rect 0.75x2.8 smd: 1(-3.81,-2.035) 2(-3.81,2.035) 3(-2.54,-2.035) 4(-2.54,2.035) 5(-1.27,-2.035) 6(-1.27,2.035) 7(0,-2.035) 8(0,2.035) 9(1.27,-2.035) 10(1.27,2.035) 11(2.54,-2.035) 12(2.54,2.035) 13(3.81,-2.035) 14(3.81,2.035)
  round 0.5 hole 1 unplated: ""(-3.175,0) ""(3.175,0)
  silkscreen extent -6.7,-2.7 6.7,1.8, body extent -6.54,-7.87 6.54,2.92, height 8.09
SMB [mm] "DO-214-AA/SMB; 2 C-Bend Leads; Body 5.3 x 3.6 mm, inc. leads (LxW)"
  rect 2.3x2.3 smd: 1(-2.25,0) 2(2.25,0)
  silkscreen extent -3.8,-1.55 4.1,1.55
SOIC-8 [mm]
  rect 1.45x0.6 smd: 1(-2.725,1.905)
  rrect50% 1.45x0.6 smd: 2(-2.725,0.635) 3(-2.725,-0.635) 4(-2.725,-1.905) 5(2.725,-1.905) 6(2.725,-0.635) 7(2.725,0.635) 8(2.725,1.905)
  silkscreen extent -2.85,-2.5 1.6,2.88, body extent -3,-2.45 3,2.45, height 1.75
ST25R3916-QFN32_5X5_0.5 [mm]
  oval 0.75x0.25 smd paste-0.015 mask+0.05: 1(-2.5,1.75) 2(-2.5,1.25) 3(-2.5,0.75) 4(-2.5,0.25) 5(-2.5,-0.25) 6(-2.5,-0.75) 7(-2.5,-1.25) 8(-2.5,-1.75) 17(2.5,-1.75) 18(2.5,-1.25) 19(2.5,-0.75) 20(2.5,-0.25) 21(2.5,0.25) 22(2.5,0.75) 23(2.5,1.25) 24(2.5,1.75)
  oval 0.25x0.75 smd paste-0.015 mask+0.05: 9(-1.75,-2.5) 10(-1.25,-2.5) 11(-0.75,-2.5) 12(-0.25,-2.5) 13(0.25,-2.5) 14(0.75,-2.5) 15(1.25,-2.5) 16(1.75,-2.5) 25(1.75,2.5) 26(1.25,2.5) 27(0.75,2.5) 28(0.25,2.5) 29(-0.25,2.5) 30(-0.75,2.5) 31(-1.25,2.5) 32(-1.75,2.5)
  rect 3.5x3.6 smd paste-10 mask+0.05: 33(0,0)
  silkscreen extent -3.3,-2.54 2.54,2.54, body extent -2.5,-2.5 2.5,2.5, height 0.85
ST-ST0201 [mm]
  rect 0.3x0.44 smd: A(0,-0.3) K(0,0.3)
  silkscreen extent -0.25,0.75 0.25,1.25, body extent -0.18,-0.33 0.18,0.33, height 0.33
"STD1802 DPAK" [mm] "D-PAK, 4-Pads, Body 6,20x6,72mm (max), IPC Medium Density"
  rect 1.9x1 smd: 1(-4.4,2.25) 2(-4.4,0) 3(-4.4,-2.25)
  rect 6.9x5.5 smd: 4(1.9,0)
  silkscreen extent -4.52,-3.35 -1.95,3.42, body extent -2.1,-3.35 4.1,3.35, height 2.38
"STM32L476VGT6 LQFP100" [mm] "TSQFP, 100-Leads, Body 14,00x14,00mm, Pitch 0,50mm, IPC Medium Density"
  oval 1.2x0.3 smd paste-0.019: 1(-7.725,6) 2(-7.725,5.5) 3(-7.725,5) 4(-7.725,4.5) 5(-7.725,4) 6(-7.725,3.5) 7(-7.725,3) 8(-7.725,2.5) 9(-7.725,2) 10(-7.725,1.5) 11(-7.725,1) 12(-7.725,0.5) 13(-7.725,0) 14(-7.725,-0.5) 15(-7.725,-1) 16(-7.725,-1.5) 17(-7.725,-2) 18(-7.725,-2.5) 19(-7.725,-3) 20(-7.725,-3.5) 21(-7.725,-4) 22(-7.725,-4.5) 23(-7.725,-5) 24(-7.725,-5.5) 25(-7.725,-6) 51(7.725,-6) 52(7.725,-5.5) 53(7.725,-5) 54(7.725,-4.5) 55(7.725,-4) 56(7.725,-3.5) 57(7.725,-3) 58(7.725,-2.5) 59(7.725,-2) 60(7.725,-1.5) 61(7.725,-1) 62(7.725,-0.5) 63(7.725,0) 64(7.725,0.5) 65(7.725,1) 66(7.725,1.5) 67(7.725,2) 68(7.725,2.5) 69(7.725,3) 70(7.725,3.5) 71(7.725,4) 72(7.725,4.5) 73(7.725,5) 74(7.725,5.5) 75(7.725,6)
  oval 0.3x1.2 smd paste-0.019: 26(-6,-7.725) 27(-5.5,-7.725) 28(-5,-7.725) 29(-4.5,-7.725) 30(-4,-7.725) 31(-3.5,-7.725) 32(-3,-7.725) 33(-2.5,-7.725) 34(-2,-7.725) 35(-1.5,-7.725) 36(-1,-7.725) 37(-0.5,-7.725) 38(0,-7.725) 39(0.5,-7.725) 40(1,-7.725) 41(1.5,-7.725) 42(2,-7.725) 43(2.5,-7.725) 44(3,-7.725) 45(3.5,-7.725) 46(4,-7.725) 47(4.5,-7.725) 48(5,-7.725) 49(5.5,-7.725) 50(6,-7.725) 76(6,7.725) 77(5.5,7.725) 78(5,7.725) 79(4.5,7.725) 80(4,7.725) 81(3.5,7.725) 82(3,7.725) 83(2.5,7.725) 84(2,7.725) 85(1.5,7.725) 86(1,7.725) 87(0.5,7.725) 88(0,7.725) 89(-0.5,7.725) 90(-1,7.725) 91(-1.5,7.725) 92(-2,7.725) 93(-2.5,7.725) 94(-3,7.725) 95(-3.5,7.725) 96(-4,7.725) 97(-4.5,7.725) 98(-5,7.725) 99(-5.5,7.725) 100(-6,7.725)
  silkscreen extent -7.85,-6.6 6.6,6.82, body extent -8,-8 8,8, height 1.6
STM-SMB_P_V [mm] "SMB, 2-Leads, Body 4.325x3.625mm"
  rect 1.62x2.18 smd: 1(-2.11,0) 2(2.11,0)
  silkscreen extent -2.3,-1.97 3.42,1.97, body extent -2.16,-1.81 2.16,1.81, height 2.59
"STT6N3LLH6 SOT23-6L" [mm]
  rect 1x0.6 smd: 1(-1.365,0.95) 2(-1.365,0) 3(-1.365,-0.95) 4(1.365,-0.95) 5(1.365,0) 6(1.365,0.95)
  silkscreen extent -1.49,-1.5 0.45,1.92, body extent -0.87,-1.51 0.86,1.52, height 1.25
SW_SPST_KMR211G [mm] "Micromineature Tactile Switch for SMT"
  rect 1.7x0.8 smd paste+0 mask+0: 0(-2.05,0.4)
  rect 0.9x1 smd paste+0 mask+0: 1(0,0) 2(0,-1.6) 3(-4.1,0) 4(-4.1,-1.6)
  silkscreen extent -4.27,-2.31 0.15,0.74, body extent -4.36,-2.19 0.24,0.61, height 1.9
"TERMINAL MKDS 1/ 3-3.81" [mm]
  rect 2.2x2.6 hole 1.1: 1(3.81,0)
  oval 2.2x2.6 hole 1.1: 2(0,0) 3(-3.81,0)
  silkscreen extent -5.71,-3.7 5.71,3.6, body extent -5.71,-3.7 5.72,3.6, height 8.55
TESTPOINT_BLACK [mm]
  round 2 hole 1.1: 1(0,0)
  body extent -1.27,-1.27 1.27,1.27, height 4.57
TESTPOINT_RED [mm]
  round 2 hole 1.1: 1(0,0)
  body extent -1.27,-1.27 1.27,1.27, height 4.57
TI-DBV5_N [mm] "SOT23, 5-Leads, Body 2.9x1.6mm, Pitch 0.95mm, IPC Medium Density"
  rect 1.1x0.6 smd: 1(-1.2,0.95) 2(-1.2,0) 3(-1.2,-0.95) 4(1.2,-0.95) 5(1.2,0.95)
  silkscreen extent -1.32,-1.55 0.25,1.92, body extent -0.87,-1.52 0.87,1.53, height 1.45
"TO-252 DPAK" [mm] "D-PAK, 3-Pads, Body 8,15x6,66mm (max), IPC Medium Density"
  rect 0.95x2.2 smd: 1(-2.28,-4.4) 3(2.28,-4.4)
  rect 6.8x7 smd: 2(0,2.1)
  silkscreen extent -3.42,-4.52 3.3,-1.55, body extent -3.27,-4.81 3.27,5.13, height 2.39
TP_0.5 [mm] "Test Point 0.5mm"
  round 0.5 smd: 1(0,0)
"U FL Socket - HRS - Surface Mount" [mm]
  rect 1x1 smd: 1(1,0)
  rect 2.2x1.05 smd: 2(-0.5,1.4) 3(-0.5,-1.4)
  body extent -1.3,-1.27 1.22,1.27, height 1.26
"WE-PD 1050" [mm] "SMD Inductor, 2-Leads, Body 10,0x10,0mm"
  rect 2x3.5 smd: 1(-4.5,0) 2(4.5,0)
  silkscreen extent -5.25,-5.2 5.25,5.2, body extent -5,-5 5,5, height 4.75
WE-PD-L [mm] "SMD Inductor, 2-Leads, Body 12.0 x 12.0 mm"
  rect 2.9x5.4 smd: 1(-4.95,0) 2(4.95,0)
  silkscreen extent -6.25,-6.25 6.25,6.25, body extent -6,-6 6,6, height 5.98
"Wurth Cooktop Balun" [mm]
  rect 2.6x1 smd: 1(-8.2,5.08) 2(-8.2,2.54) 3(-8.2,0) 4(-8.2,-2.54) 5(-8.2,-5.08) 6(8.2,-5.08) 7(8.2,-2.54) 8(8.2,0) 9(8.2,2.54) 10(8.2,5.08)
  silkscreen extent -8.35,-6.6 7.25,6.6, body extent -8.87,-6.75 8.87,6.75, height 12.6
XRCGB_F_MN [mm]
  rect 0.75x0.7 smd mask+0.1: 1(0.675,0.527) 2(-0.675,0.527) 3(-0.675,-0.525) 4(0.675,-0.525)
  silkscreen extent -1.22,-1.05 1.22,1.05, body extent -1,-0.8 1,0.8, height 0.7
XSON6_SOT1202 [mm]
  rect 0.65x0.15 smd: 1(-0.515,0.35) 2(-0.515,0) 3(-0.515,-0.35) 4(0.515,-0.35) 5(0.515,0) 6(0.515,0.35)
  silkscreen extent -1.1,0.59 -1,0.69, body extent -0.53,-0.53 0.53,0.53, height 0.35

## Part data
AAT_A600 AAT_B600 CSI600 CSO600 TP600 TP601 TP603: library part "Test point 0.5mm"
BootL400 Reset400: library part SW_SPST2_GND, "SWITCH TACTILE SPST-NO 0.05A 32V", Contact Current Rating=50mA, Manufacturer="ITT C&K", Manufacturer Part Number=KMR211GLFS, Max Operating Temperature=85°C, Max Voltage Rating (DC)=32V, Min Operating Temperature=-40°C, Operating Force=1.2N, Package Quantity=1, Power Rating=1W, Supplier Part Number 1=401-1426-1-ND
C300: library part "CAP P", "Alum. Electrolytic Cap 100µF 63V 10mm Radial WCAP-ATUL; Lifetime 7000h +105°C", Case/Package=Radial, Manufacturer="Würth Electronics", Manufacturer 1="Wurth Electronics", Manufacturer Part Number=860040775006, Max Operating Temperature=105°C, Min Operating Temperature=-40°C, Package Quantity=600, Ripple Current=640mA, Supplier Part Number 1=2465902, Voltage Rating=63V
C301 C305 C310 C318 C320 C323: library part "CAP NP", "Capacitor", Package=TBD, Supplier Part Number 1=1740673
C302: library part "CAP NP", "Capacitor", Package=TBD, Supplier Part Number 1=1740621
C303 C304 C306 C312 C314 C315 C316 C317: library part "CAP NP", "Capacitor", Package=TBD, Supplier Part Number 1=3340869
C307 C309 C311 C313 C321 C322: library part "CAP NP", "Capacitor", Package=TBD, Supplier Part Number 1=478-5995-1-ND
C308 C319: library part "CAP NP", "Ceramic Capacitor, Multilayer, Ceramic, 50V, 5% +Tol, 5% -Tol, C0G, 30ppm/Cel TC, 0.00001uF, Surface Mount, 0805", Capacitor Type=Ceramic, Manufacturer="Kyocera AVX", Manufacturer Part Number=08055A100JAT2A, Max Operating Temperature=125°C, Min Operating Temperature=-55°C, Negative Tolerance=5%, Package Shape=Rectangular, Package Style=SMTMeter, Rated DC Voltage (URdc)=50V, Supplier Part Number 1=478-1304-1-ND, Temperature Characteristics Code=C0G
C400 C402: library part C_0402, "CAPACITOR CERAMIC 18PF 50V, C0G, 5%, 040", Case Code (Imperial)=0402, Case Code (Metric)=1005, Dielectric=C0G, Dielectric Material=Ceramic, Insulation Resistance=100GR, Manufacturer="Kyocera AVX", Manufacturer Part Number=04025A180JAT2A, Max Operating Temperature=125°C, Min Operating Temperature=-55°C, Package Quantity=1, Supplier Part Number 1=478-1073-6-ND, Temperature Coefficient=0ppm/°C, Tolerance=5%, Voltage=50V
C401 C403: library part C_0603, "Capacitor 100 nF 10 VDC 0402", Case Code (Imperial)=0402, Case Code (Metric)=1005, Dielectric=X5R, Dielectric Material=Ceramic, Manufacturer=KEMET, Manufacturer Part Number=C0402C104K8PACTU, Max Operating Temperature=85°C, Min Operating Temperature=-55°C, Package Quantity=1, Supplier Part Number 1=399-3027-1-ND, Tolerance=10%, Voltage=10V
C404 C407: library part C_0402, Capacitance=100, Case Code (Imperial)=0402, Case Code (Metric)=1005, Manufacturer=Murata, Manufacturer Part Number=GRM155R61H104KE19D, Max Operating Temperature=125, Min Operating Temperature=-55, Supplier Part Number 1=490-11917-2-ND, Tolerance=10, Type (Capacitors)=X5R, Voltage Rating=50
C405 C406: library part C_POL_A, Capacitance=1, Case Code (Imperial)=1206, Case Code (Metric)=3216, Manufacturer="Kyocera / AVX", Manufacturer Part Number=TAJA105K016RNJ, Max Operating Temperature=125, Min Operating Temperature=-55, Package Quantity=2000, Resistance=11, Supplier Part Number 1=498701, Tolerance=10, Voltage Rating=16
C408 C409 C410 C411 C412 C413 C600: library part C_0603, Betriebstemperatur, max.=85, Betriebstemperatur, min.=-55, Kapazitätstoleranz="± 10%", Manufacturer=MURATA, Manufacturer Part Number=GRM155R61H104KE19D, Supplier Part Number 1=2218856
C601: library part C_1µ_0402_X5R, "1u_X5R", Manufacturer=MURATA, Manufacturer Part Number=GRM155R61C105KA12D, Supplier Part Number 1=2362093
C602 C608 C610 C612 C618 C621 C623 C626: library part C_10n_0402_X7R, "10n_x7R", Manufacturer=AVX, Manufacturer Part Number=04023C103KAT2A, Supplier Part Number 1=1327624
C603 C625: library part C_120p_0603, "120p_COG", Manufacturer=MURATA, Manufacturer Part Number=GRM1885C1H121GA01D, Supplier Part Number 1=490-12712-1-ND
C604 C617: library part C_10p_0603, "10p_COG", Manufacturer=MULTICOMP, Manufacturer Part Number=MC0603N100F500CT, Supplier Part Number 1=2410381
C605 C616: library part C_68p_0603, "Cap Ceramic 0.1uF 50V X7R 10% Pad SMD 0805 FlexiTerm 125C Automotive T/R", Case Code (Imperial)=0805, Case Code (Metric)=2012, Dielectric=X7R, Dielectric Material=Ceramic, Manufacturer="Kyocera AVX", Manufacturer Part Number=08055C104K4Z2A, Max Operating Temperature=125°C, Min Operating Temperature=-55°C, Package Quantity=1, Ratings=AEC-Q200, Supplier Part Number 1=478-6048-1-ND, Temperature Coefficient=30ppm/°C, Tolerance=10%, Voltage=50V
C609 C613 C622 C624 C627: library part C_2µ2_0402_X5R, "2u2_X5R", Manufacturer=MURATA, Manufacturer Part Number=GRM155R60J225ME15D, Supplier Part Number 1=2362088
C611: library part C_4µ7_0402_X5R, "4u7_X5R", Manufacturer=TDK, Manufacturer Part Number=C1005X5R0J475K050BC
C619 C620: library part C_2µ2_0402_X5R, Manufacturer=MURATA, Manufacturer Part Number=GRM155R60J225ME15D, Supplier Part Number 1=2362088
C628 C629: library part C_10p_0402, "10p_COG", Manufacturer=MURATA, Manufacturer Part Number=GRM1555C1H100GA01D, Supplier Part Number 1=490-6187-1-ND
C700: library part C_0805, "Ceramic Capacitor, Multilayer, Ceramic, 100V, 5% +Tol, 5% -Tol, C0G, 30ppm/Cel TC, 0.001uF, Surface Mount, 0805", Capacitor Type=Ceramic, Manufacturer="Kyocera AVX", Manufacturer Part Number=08051A102JAT2A, Max Operating Temperature=125°C, Min Operating Temperature=-55°C, Negative Tolerance=5%, Package Shape=Rectangular, Package Style=SMTMeter, Rated DC Voltage (URdc)=100V, Supplier Part Number 1=478-1290-1-ND, Temperature Characteristics Code=C0G
C701: library part C_0805, "Ceramic Capacitor, Multilayer, Ceramic, 25V, 10% +Tol, 10% -Tol, X5R, 15% TC, 10uF, Surface Mount, 0805", Capacitance=10uF, Capacitor Type=Ceramic, Manufacturer=Murata, Manufacturer Part Number=GRM21BR61E106KA73L, Max Operating Temperature=85°C, Min Operating Temperature=-55°C, Negative Tolerance=10%, Package Shape=Rectangular, Package Style=SMTMeter, Rated DC Voltage (URdc)=25V, Supplier Part Number 1=490-5523-2-ND, Temperature Characteristics Code=X5R
C702: library part C_0805, "Ceramic Capacitor, Ceramic, 50V, 10% +Tol, 10% -Tol, X7R, -/+15ppm/Cel TC, 0.01uF, 0805", Capacitor Type=Ceramic, Manufacturer=KEMET, Manufacturer Part Number=C0805F103K5RACTU, Max Operating Temperature=125°C, Min Operating Temperature=-55°C, Negative Tolerance=10%, Package Style=SMTMeter, Rated DC Voltage (URdc)=50V, Supplier Part Number 1=399-5107-1-ND, Temperature Characteristics Code=X7R
C703 C707: library part C_0805, "Ceramic Capacitor, Multilayer, Ceramic, 50V, 10% +Tol, 10% -Tol, X7R, 15% TC, 0.1uF, Surface Mount, 0805", Capacitor Type=Ceramic, Manufacturer="Kyocera AVX", Manufacturer Part Number=08055C104K4Z2A, Max Operating Temperature=125°C, Min Operating Temperature=-55°C, Negative Tolerance=10%, Package Shape=Rectangular, Package Style=SMTMeter, Rated DC Voltage (URdc)=50V, Supplier Part Number 1=478-6048-1-ND, Temperature Characteristics Code=X7R
C704: library part C_0805, "Ceramic Capacitor, Multilayer, Ceramic, 100V, 5% +Tol, 5% -Tol, C0G, -/+30ppm/Cel TC, 0.000068uF, Surface Mount, 0805", Capacitor Type=Ceramic, Manufacturer=KEMET, Manufacturer Part Number=C0805C680J1GACTU, Max Operating Temperature=125°C, Min Operating Temperature=-55°C, Negative Tolerance=5%, Package Shape=Rectangular, Rated DC Voltage (URdc)=100V, Supplier Part Number 1=399-C0805C680J1GAC7800CT-ND, Temperature Characteristics Code=C0G
C705: library part C_0603, "Ceramic Capacitor, Multilayer, Ceramic, 100V, 5% +Tol, 5% -Tol, C0G, 30ppm/Cel TC, 0.000015uF, Surface Mount, 0603", Capacitor Type=Ceramic, Manufacturer=KEMET, Manufacturer Part Number=C0603C150J1GACTU, Max Operating Temperature=125°C, Min Operating Temperature=-55°C, Negative Tolerance=5%, Package Shape=Rectangular, Package Style=SMTMeter, Rated DC Voltage (URdc)=100V, Supplier Part Number 1=399-C0603C150J1GAC7867CT-ND, Temperature Characteristics Code=C0G
C706 C712 C714: library part C_0603, "Ceramic Capacitor, Multilayer, Ceramic, 100V, 5% +Tol, 5% -Tol, C0G, 30ppm/Cel TC, 0.000022uF, Surface Mount, 0603", Capacitor Type=Ceramic, Manufacturer=KEMET, Manufacturer Part Number=C0603C220J1GACTU, Max Operating Temperature=125°C, Min Operating Temperature=-55°C, Negative Tolerance=5%, Package Shape=Rectangular, Package Style=SMTMeter, Rated DC Voltage (URdc)=100V, Supplier Part Number 1=399-C0603C220J1GAC7867CT-ND, Temperature Characteristics Code=C0G
C708: library part C_0603, "Ceramic Capacitor, Multilayer, Ceramic, 100V, 10% +Tol, 10% -Tol, X7R, 15% TC, 0.047uF, Surface Mount, 0603", Capacitor Type=Ceramic, Manufacturer=KEMET, Manufacturer Part Number=C0603C473K1RACTU, Max Operating Temperature=125°C, Min Operating Temperature=-55°C, Negative Tolerance=10%, Package Shape=Rectangular, Package Style=SMTMeter, Rated DC Voltage (URdc)=100V, Supplier Part Number 1=399-C0603C473K1RAC7867CT-ND, Temperature Characteristics Code=X7R
C709 C710: library part C_0805, "Ceramic Capacitor, Multilayer, Ceramic, 100V, 5% +Tol, 5% -Tol, C0G, 30ppm/Cel TC, 0.000033uF, Surface Mount, 0603", Capacitor Type=Ceramic, Manufacturer=KEMET, Manufacturer Part Number=C0603C330J1GACTU, Max Operating Temperature=125°C, Min Operating Temperature=-55°C, Negative Tolerance=5%, Package Shape=Rectangular, Package Style=SMTMeter, Rated DC Voltage (URdc)=100V, Supplier Part Number 1=399-C0603C330J1GAC7867CT-ND, Temperature Characteristics Code=C0G
C711 C716: library part C_0603, "Ceramic Capacitor, Multilayer, Ceramic, 100V, 5% +Tol, 5% -Tol, C0G, -/+30ppm/Cel TC, 0.0022uF, Surface Mount, 0603", Capacitance=2.2nF, Capacitor Type=Ceramic, Manufacturer=KEMET, Manufacturer Part Number=C0603H222J1GACTU, Max Operating Temperature=200°C, Min Operating Temperature=-55°C, Negative Tolerance=5%, Package Shape=Rectangular, Package Style=SMTMeter, Rated DC Voltage (URdc)=100V, Supplier Part Number 1=399-13264-1-ND, Temperature Characteristics Code=C0G
C713 C715: library part C_0603, "Ceramic Capacitor, Multilayer, Ceramic, 100V, 5% +Tol, 5% -Tol, C0G, 30ppm/Cel TC, 0.00013uF, Surface Mount, 0603", Capacitor Type=Ceramic, Manufacturer=Murata, Manufacturer Part Number=GRM1885C2A131JA01D, Max Operating Temperature=125°C, Min Operating Temperature=-55°C, Negative Tolerance=5%, Package Shape=Rectangular, Package Style=SMTMeter, Rated DC Voltage (URdc)=100V, Supplier Part Number 1=490-1354-1-ND, Temperature Characteristics Code=C0G
D300: library part "D Schottky", "Diode Schottky 40V 2A DO214AC Sm", Manufacturer=Comchip, Manufacturer Part Number=SS24-HF, Supplier Part Number 1=641-SS24-HFCT-ND
D500 D501: "ESD PROTECT TRANSIL ESDALC6V1-1U2", Manufacturer="ST MICRO", Supplier Part Number 1=32R9998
